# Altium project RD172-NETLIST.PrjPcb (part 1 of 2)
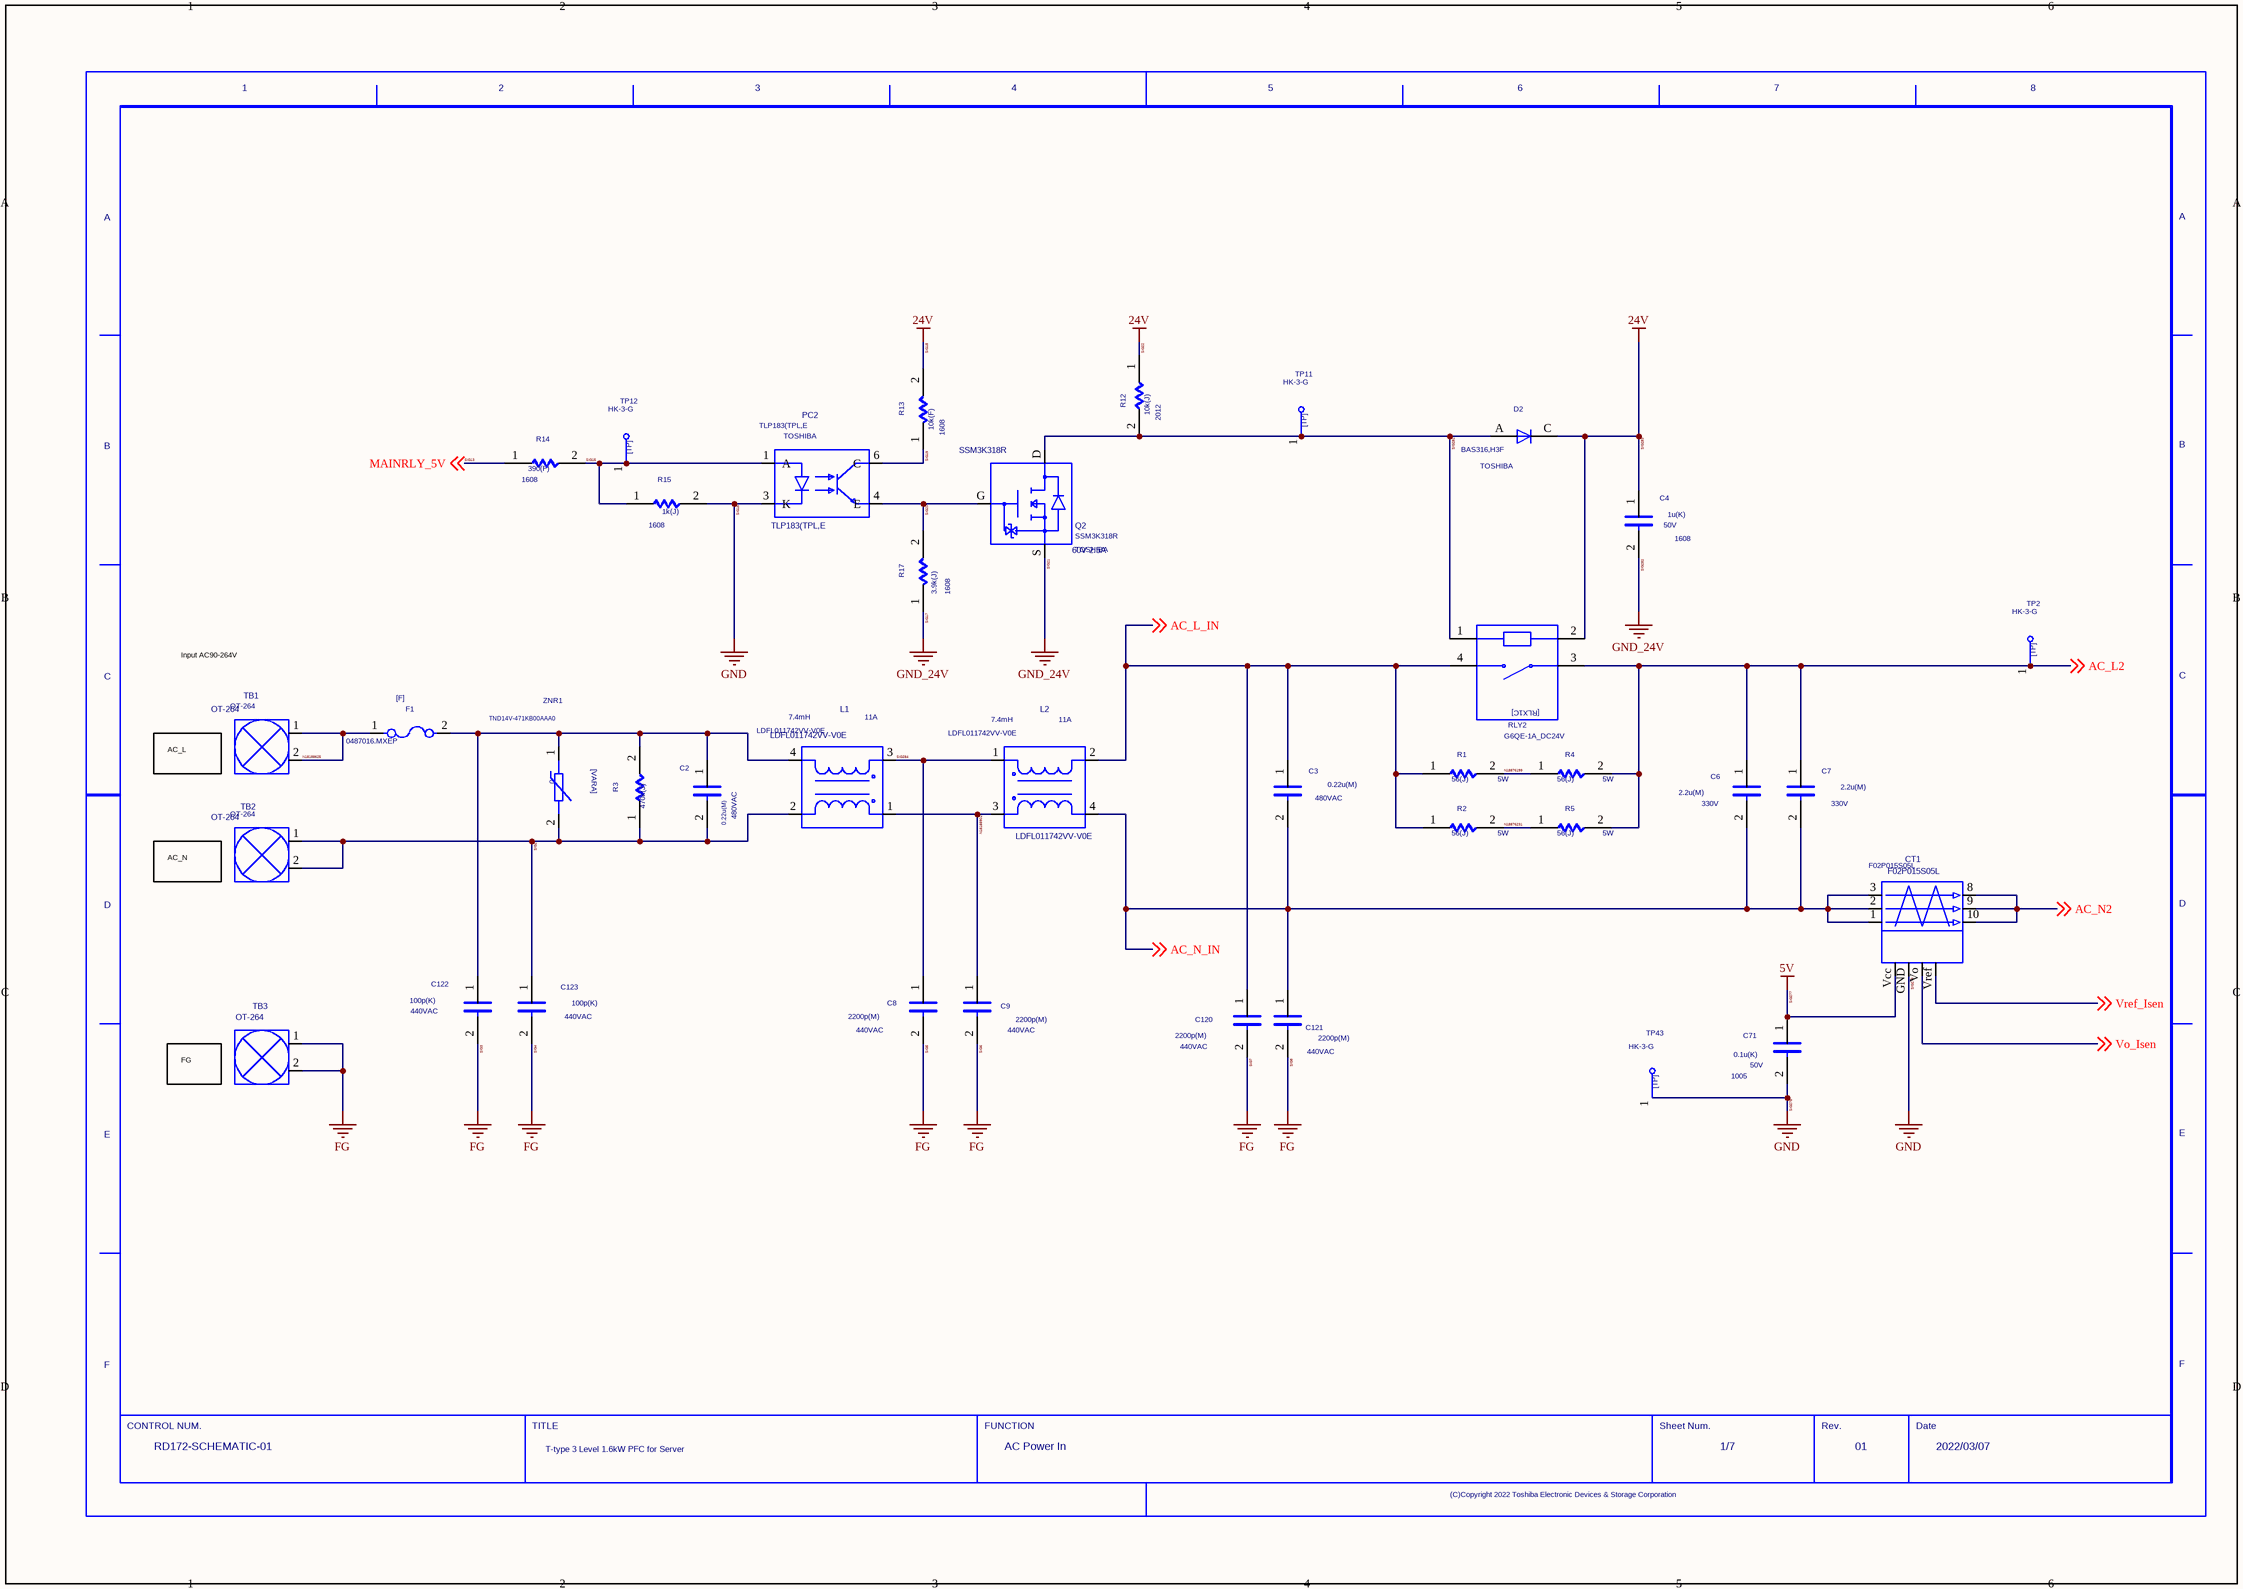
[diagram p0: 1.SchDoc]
7 sheets, 376 parts. Net scope: global (net labels, ports and power ports of the same name join across sheets).
Sheets:
  1.SchDoc
  2.SchDoc
  3.SchDoc
  4.SchDoc
  5.SchDoc
  6.SchDoc
  7.SchDoc

## Sheet 1.SchDoc
size 420 x 297 mm

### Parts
(Parts that share a designator on the sheet are numbered #1, #2 ... from top to bottom, then left to right.)
C2  VAL2: 480VAC  VAL1: 0.22u(M)  (hidden comment: C)
C3  VAL2: 480VAC  VAL1: 0.22u(M)  (hidden comment: C)
C4  SIZECODESMD: 1608  VAL2: 50V  VAL1: 1u(K)  (hidden comment: C)
C6  VAL2: 330V  VAL1: 2.2u(M)  (hidden comment: C)
C7  VAL2: 330V  VAL1: 2.2u(M)  (hidden comment: C)
C8  VAL2: 440VAC  VAL1: 2200p(M)  (hidden comment: C)
C9  VAL2: 440VAC  VAL1: 2200p(M)  (hidden comment: C)
C71  SIZECODESMD: 1005  VAL2: 50V  VAL1: 0.1u(K)  (hidden comment: C)
C120  VAL2: 440VAC  VAL1: 2200p(M)  (hidden comment: C)
C121  VAL2: 440VAC  VAL1: 2200p(M)  (hidden comment: C)
C122  VAL2: 440VAC  VAL1: 100p(K)  (hidden comment: C)
C123  VAL2: 440VAC  VAL1: 100p(K)  (hidden comment: C)
CT1  F02P015S05L
D2  VAL3: BAS316,H3F  USERCOMPTEXT3: TOSHIBA  (hidden comment: D)
F1  VAL3: 0487016.MXEP  (hidden comment: F)
L1  LDFL011742VV-V0E  VAL1: 7.4mH
L2  LDFL011742VV-V0E  VAL1: 7.4mH
PC2  TLP183(TPL,E  USERCOMPTEXT3: TOSHIBA
Q2  SSM3K318R  NOTE: 60V 2.5A  USERCOMPTEXT3: TOSHIBA
R1  VAL2: 5W  VAL1: 56(J)  (hidden comment: R)
R2  VAL2: 5W  VAL1: 56(J)  (hidden comment: R)
R3  VAL1: 470k(J)  (hidden comment: R)
R4  VAL2: 5W  VAL1: 56(J)  (hidden comment: R)
R5  VAL2: 5W  VAL1: 56(J)  (hidden comment: R)
R12  SIZECODESMD: 2012  VAL1: 10k(J)  (hidden comment: R)
R13  SIZECODESMD: 1608  VAL1: 10k(F)  (hidden comment: R)
R14  SIZECODESMD: 1608  VAL1: 390(F)  (hidden comment: R)
R15  SIZECODESMD: 1608  VAL1: 1k(J)  (hidden comment: R)
R17  SIZECODESMD: 1608  VAL1: 3.9k(J)  (hidden comment: R)
RLY2  VAL3: G6QE-1A_DC24V  (hidden comment: RLX1C)
TB1  OT-264
TB2  OT-264
TB3  OT-264
TP2  VAL3: HK-3-G  (hidden comment: TP)
TP11  VAL3: HK-3-G  (hidden comment: TP)
TP12  VAL3: HK-3-G  (hidden comment: TP)
TP43  VAL3: HK-3-G  (hidden comment: TP)
U?#1  DATE: 2022/03/07  DRAWINGNUMBER: RD172-SCHEMATIC-01  REVISION: 01  SHEETNUMBER: 1/7  TITLE: T-type 3 Level 1.6kW PFC for Server  FUNCTION: AC Power In  (hidden comment: WAKU_DEF100)
ZNR1  VAL3: TND14V-471KB00AAA0  (hidden comment: VARA)

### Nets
5V: C71.1 CT1.Vcc(VCC)  [also labelled SIG277]  [project net SIG177]
GND: C71.2 CT1.GND PC2.3(K) R15.2 TP43.1  [also labelled SIG16, SIG275, SIG278]  [project net SIG157]
SIG3: C8.2 C9.2 C120.2 C121.2 C122.2 C123.2 TB3.1 TB3.2  [also labelled FG, SIG4, SIG5, SIG6, SIG7, SIG8]
SIG17: C4.2 Q2.S R17.1  [also labelled GND_24V, SIG21, SIG282]
SIG18: C4.1 D2.C R12.1 R13.2 RLY2.2  [also labelled 24V, SIG22, SIG283]
AC_L2: C6.1 C7.1 R4.2 R5.2 RLY2.3 TP2.1 ; off-sheet AC_L2
AC_L_IN: C3.1 C120.1 L2.2 R1.1 R2.1 RLY2.4 ; off-sheet AC_L_IN
AC_N2: CT1.8 CT1.9 CT1.10 ; off-sheet AC_N2
AC_N_IN: C3.2 C6.2 C7.2 C121.1 CT1.1 CT1.2 CT1.3 L2.4 ; off-sheet AC_N_IN
N18188625: F1.1 TB1.1 TB1.2
N18188901: C9.1 L1.1 L2.3
N18876199: R1.2 R4.1
N18876231: R2.2 R5.1
SIG1: C2.1 C122.1 F1.2 L1.4 R3.2 ZNR1.1
SIG2: C2.2 C123.1 L1.2 R3.1 TB2.1 TB2.2 ZNR1.2
SIG13: R14.1 ; off-sheet MAINRLY_5V  [also labelled MAINRLY_5V]
SIG15: PC2.1(A) R14.2 R15.1 TP12.1
SIG19: PC2.6(C) R13.1
SIG20: PC2.4(E) Q2.G R17.2
SIG281: D2.A Q2.D R12.2 RLY2.1 TP11.1
SIG284: C8.1 L1.3 L2.1
Vo_Isen: CT1.Vo ; off-sheet Vo_Isen
Vref_Isen: CT1.Vref ; off-sheet Vref_Isen

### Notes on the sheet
- Input AC90-264V
- AC_L
- AC_N
- FG

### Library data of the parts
C2 C3 = C: OriginalSymbolOrigin: (2540,7620); COMP: -C-F339X142248MIP2T0
C4 = C: OriginalSymbolOrigin: (2540,7620); COMP: -C-UMK107AB7105KA-T
C6 C7 = C: OriginalSymbolOrigin: (2540,7620); COMP: -C-B32914A3225M000
C8 C9 C120 C121 = C: OriginalSymbolOrigin: (2540,7620); COMP: -C-CD45-E2GA222M-VKA
C71 = C: OriginalSymbolOrigin: (2540,7620); COMP: -C-UMK105BJ104KV-F
C122 C123 = C: OriginalSymbolOrigin: (2540,7620); COMP: -C-CD45-B2GA101K-VKA
CT1 = F02P015S05L: Current Transducer, 15A; MANUFACTURER: Tamura; COMP: -CT-F02P015S05L_PIN; TIME: 16:53:55; UPDATEUSER: t5459927; UPDATETIME: 16:08:01; SAVECOUNT: 2; SAVEAREA0: -5739,-18135,20354,994; OriginalSymbolOrigin: (0,0)
D2 = D: SAVEAREA0: -225,-91,12804,7836; SAVECOUNT: 3; TIME: 14:49:55; UPDATEUSER: 19870035; UPDATETIME: 14:20:16; OriginalSymbolOrigin: (5080,5080); COMP: -D-BAS316_H3F_AC
F1 = F: OriginalSymbolOrigin: (2540,5080); COMP: -F-0487016MXEP
L1 L2 = LDFL011742VV_V0E: 11A; MANUFACTURER: Nippon Chemi-Con; COMP: -L-LDFL011742VV-V0E; TIME: 16:53:58; UPDATEUSER: t5459927; SAVECOUNT: 1; SAVEAREA0: -3836,-15544,18528,852; OriginalSymbolOrigin: (0,0); INSTANCENAME: INS18188789
PC2 = TLP183_TPL_E: Photocoupler; COMP: -PC-TLP183_TPL_E; TIME: 16:53:54; UPDATEUSER: t5459927; UPDATETIME: 16:20:20; SAVECOUNT: 2; SAVEAREA0: -3467,-14897,20665,2795; OriginalSymbolOrigin: (0,0)
Q2 = SSM3K318R: MOSFET; COMP: -Q-SSM3K318R_LF; TIME: 16:53:56; UPDATEUSER: t5459927; UPDATETIME: 14:46:06; SAVECOUNT: 2; SAVEAREA0: -8920,-18190,20901,3672; OriginalSymbolOrigin: (0,0)
R1 R2 R4 R5 = R: OriginalSymbolOrigin: (5080,5080); COMP: -R-SQMW556RJ
R3 = R: OriginalSymbolOrigin: (5080,5080); VAL2: 1W; COMP: -R-RCR60C474J
R12 = R: OriginalSymbolOrigin: (5080,5080); COMP: -R-RK73B2ATTD103J; VAL2: 250mW
R13 = R: OriginalSymbolOrigin: (5080,5080); COMP: -R-ERJ3EKF1002V; VAL2: 100mW
R14 = R: OriginalSymbolOrigin: (5080,5080); COMP: -R-ERJ3EKF3900V; VAL2: 100mW
R15 = R: OriginalSymbolOrigin: (5080,5080); COMP: -R-RK73B1JTTD102J; VAL2: 125mW
R17 = R: OriginalSymbolOrigin: (5080,5080); COMP: -R-RK73B1JTTD392J; VAL2: 100mW
RLY2 = RLX1C: SAVECOUNT: 9; SAVEAREA0: -9347,-440,34039,23986; OriginalSymbolOrigin: (5080,20320); COMP: -RL-G6QE-1A_DC24
TB1 = OT_264: Terminal, 50A, M4; MANUFACTURER: Osada; COMP: -TB-OT-264; TIME: 16:53:54; UPDATEUSER: t5459927; SAVECOUNT: 1; SAVEAREA0: -3825,-10384,11084,546; OriginalSymbolOrigin: (0,0); REFERENCE TEMPLATE: TB; INSTANCENAME: INS18188586
TB2 = OT_264: Terminal, 50A, M4; MANUFACTURER: Osada; COMP: -TB-OT-264; TIME: 16:53:54; UPDATEUSER: t5459927; SAVECOUNT: 1; SAVEAREA0: -3825,-10384,11084,546; OriginalSymbolOrigin: (0,0); REFERENCE TEMPLATE: TB; INSTANCENAME: INS18188886
TB3 = OT_264: Terminal, 50A, M4; MANUFACTURER: Osada; COMP: -TB-OT-264; TIME: 16:53:54; UPDATEUSER: t5459927; UPDATETIME: 16:17:50; SAVECOUNT: 2; SAVEAREA0: -3825,-10384,11084,546; OriginalSymbolOrigin: (0,0)
TP2 TP11 TP12 TP43 = TP: TIME: 16:12:21; UPDATEUSER: fukuda-y; UPDATETIME: 16:18:11; SAVECOUNT: 2; SAVEAREA0: -242,-92,12810,7836; OriginalSymbolOrigin: (0,7620); COMP: -TP-HK-3-G
U?#1 = WAKU_DEF100: PLOTTIME: HH:MM; SAVEAREA0: 148187,-66180,486823,89919; TIME: 14:30:25; UPDATEUSER: t5459927; UPDATETIME: 09:34:25; SAVECOUNT: 6; OriginalSymbolOrigin: (10160,284480)
ZNR1 = VARA: SAVEAREA0: -9950,-8554,25168,13619; SAVECOUNT: 12; TIME: 09:56:50; UPDATEUSER: tomizawa-y; OriginalSymbolOrigin: (2540,5080); COMP: -ZNR-TND14V-471KB00AAA0

## Sheet 2.SchDoc
size 420 x 297 mm
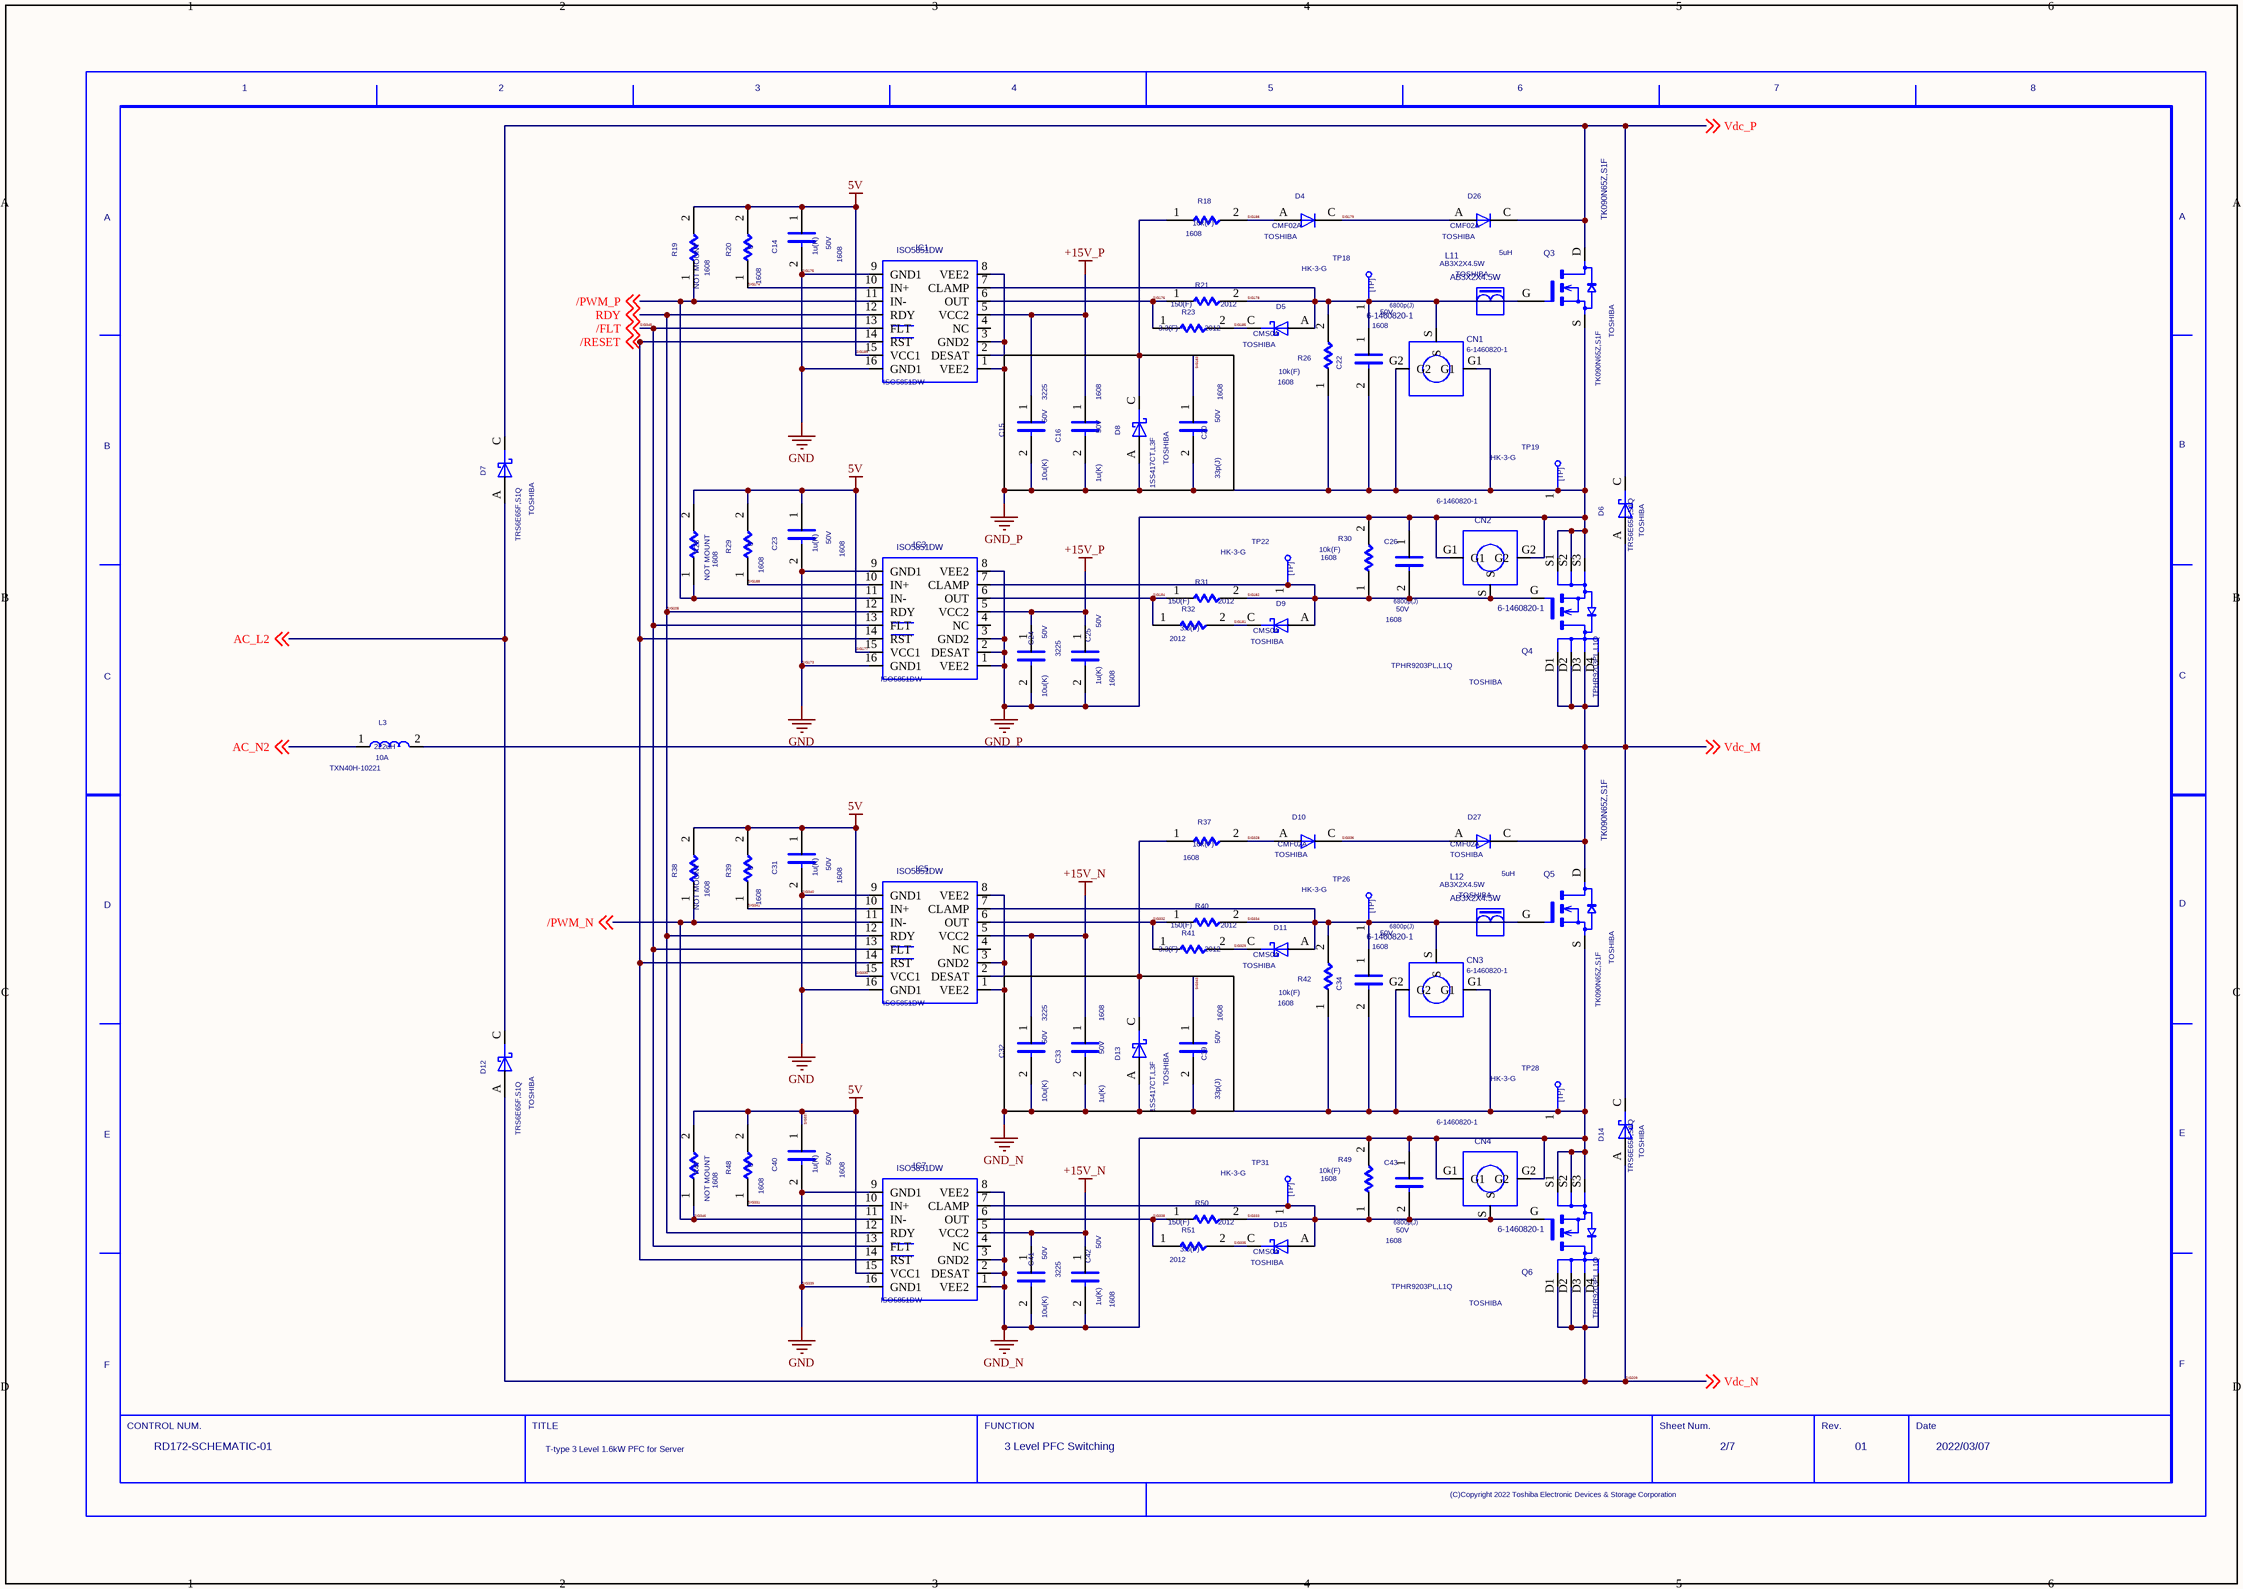
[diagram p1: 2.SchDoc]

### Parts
(Parts that share a designator on the sheet are numbered #1, #2 ... from top to bottom, then left to right.)
C14  SIZECODESMD: 1608  VAL2: 50V  VAL1: 1u(K)  (hidden comment: C)
C15  SIZECODESMD: 3225  VAL2: 50V  VAL1: 10u(K)  (hidden comment: C)
C16  SIZECODESMD: 1608  VAL2: 50V  VAL1: 1u(K)  (hidden comment: C)
C20  SIZECODESMD: 1608  VAL2: 50V  VAL1: 33p(J)  (hidden comment: C)
C22  SIZECODESMD: 1608  VAL2: 50V  VAL1: 6800p(J)  (hidden comment: C)
C23  SIZECODESMD: 1608  VAL2: 50V  VAL1: 1u(K)  (hidden comment: C)
C24  SIZECODESMD: 3225  VAL2: 50V  VAL1: 10u(K)  (hidden comment: C)
C25  SIZECODESMD: 1608  VAL2: 50V  VAL1: 1u(K)  (hidden comment: C)
C26  SIZECODESMD: 1608  VAL2: 50V  VAL1: 6800p(J)  (hidden comment: C)
C31  SIZECODESMD: 1608  VAL2: 50V  VAL1: 1u(K)  (hidden comment: C)
C32  SIZECODESMD: 3225  VAL2: 50V  VAL1: 10u(K)  (hidden comment: C)
C33  SIZECODESMD: 1608  VAL2: 50V  VAL1: 1u(K)  (hidden comment: C)
C34  SIZECODESMD: 1608  VAL2: 50V  VAL1: 6800p(J)  (hidden comment: C)
C39  SIZECODESMD: 1608  VAL2: 50V  VAL1: 33p(J)  (hidden comment: C)
C40  SIZECODESMD: 1608  VAL2: 50V  VAL1: 1u(K)  (hidden comment: C)
C41  SIZECODESMD: 3225  VAL2: 50V  VAL1: 10u(K)  (hidden comment: C)
C42  SIZECODESMD: 1608  VAL2: 50V  VAL1: 1u(K)  (hidden comment: C)
C43  SIZECODESMD: 1608  VAL2: 50V  VAL1: 6800p(J)  (hidden comment: C)
CN1  6-1460820-1
CN2  6-1460820-1
CN3  6-1460820-1
CN4  6-1460820-1
D4  VAL3: CMF02A  USERCOMPTEXT3: TOSHIBA  (hidden comment: D)
D5  USERCOMPTEXT3: TOSHIBA  VAL3: CMS04  (hidden comment: SBD)
D6  VAL3: TRS6E65F,S1Q  USERCOMPTEXT3: TOSHIBA  (hidden comment: SBD)
D7  USERCOMPTEXT3: TOSHIBA  VAL3: TRS6E65F,S1Q  (hidden comment: SBD)
D8  USERCOMPTEXT3: TOSHIBA  VAL3: 1SS417CT,L3F  (hidden comment: SBD)
D9  USERCOMPTEXT3: TOSHIBA  VAL3: CMS04  (hidden comment: SBD)
D10  VAL3: CMF02A  USERCOMPTEXT3: TOSHIBA  (hidden comment: D)
D11  USERCOMPTEXT3: TOSHIBA  VAL3: CMS04  (hidden comment: SBD)
D12  USERCOMPTEXT3: TOSHIBA  VAL3: TRS6E65F,S1Q  (hidden comment: SBD)
D13  USERCOMPTEXT3: TOSHIBA  VAL3: 1SS417CT,L3F  (hidden comment: SBD)
D14  VAL3: TRS6E65F,S1Q  USERCOMPTEXT3: TOSHIBA  (hidden comment: SBD)
D15  USERCOMPTEXT3: TOSHIBA  VAL3: CMS04  (hidden comment: SBD)
D26  VAL3: CMF02A  USERCOMPTEXT3: TOSHIBA  (hidden comment: D)
D27  VAL3: CMF02A  USERCOMPTEXT3: TOSHIBA  (hidden comment: D)
IC1  ISO5851DW
IC3  ISO5851DW
IC5  ISO5851DW
IC7  ISO5851DW
L3  VAL3: TXN40H-10221  VAL2: 10A  VAL1: 222uH  (hidden comment: L)
L11  AB3X2X4.5W  USERCOMPTEXT3: TOSHIBA  VAL1: 5uH
L12  AB3X2X4.5W  USERCOMPTEXT3: TOSHIBA  VAL1: 5uH
Q3  TK090N65Z,S1F  USERCOMPTEXT3: TOSHIBA
Q4  TPHR9203PL,L1Q  USERCOMPTEXT3: TOSHIBA
Q5  TK090N65Z,S1F  USERCOMPTEXT3: TOSHIBA
Q6  TPHR9203PL,L1Q  USERCOMPTEXT3: TOSHIBA
R18  SIZECODESMD: 1608  VAL1: 10k(F)  (hidden comment: R)
R19  SIZECODESMD: 1608  NOTMOUNT: NOT MOUNT  (hidden comment: R)
R20  SIZECODESMD: 1608  VAL1: 0  (hidden comment: R)
R21  SIZECODESMD: 2012  VAL1: 150(F)  (hidden comment: R)
R23  SIZECODESMD: 2012  VAL1: 3.3(F)  (hidden comment: R)
R26  SIZECODESMD: 1608  VAL1: 10k(F)  (hidden comment: R)
R28  SIZECODESMD: 1608  NOTMOUNT: NOT MOUNT  (hidden comment: R)
R29  SIZECODESMD: 1608  VAL1: 0  (hidden comment: R)
R30  SIZECODESMD: 1608  VAL1: 10k(F)  (hidden comment: R)
R31  SIZECODESMD: 2012  VAL1: 150(F)  (hidden comment: R)
R32  SIZECODESMD: 2012  VAL1: 3.3(F)  (hidden comment: R)
R37  SIZECODESMD: 1608  VAL1: 10k(F)  (hidden comment: R)
R38  SIZECODESMD: 1608  NOTMOUNT: NOT MOUNT  (hidden comment: R)
R39  SIZECODESMD: 1608  VAL1: 0  (hidden comment: R)
R40  SIZECODESMD: 2012  VAL1: 150(F)  (hidden comment: R)
R41  SIZECODESMD: 2012  VAL1: 3.3(F)  (hidden comment: R)
R42  SIZECODESMD: 1608  VAL1: 10k(F)  (hidden comment: R)
R47  SIZECODESMD: 1608  NOTMOUNT: NOT MOUNT  (hidden comment: R)
R48  SIZECODESMD: 1608  VAL1: 0  (hidden comment: R)
R49  SIZECODESMD: 1608  VAL1: 10k(F)  (hidden comment: R)
R50  SIZECODESMD: 2012  VAL1: 150(F)  (hidden comment: R)
R51  SIZECODESMD: 2012  VAL1: 3.3(F)  (hidden comment: R)
TP18  VAL3: HK-3-G  (hidden comment: TP)
TP19  VAL3: HK-3-G  (hidden comment: TP)
TP22  VAL3: HK-3-G  (hidden comment: TP)
TP26  VAL3: HK-3-G  (hidden comment: TP)
TP28  VAL3: HK-3-G  (hidden comment: TP)
TP31  VAL3: HK-3-G  (hidden comment: TP)
U?#2  DATE: 2022/03/07  REVISION: 01  SHEETNUMBER: 2/7  FUNCTION: 3 Level PFC Switching  TITLE: T-type 3 Level 1.6kW PFC for Server  DRAWINGNUMBER: RD172-SCHEMATIC-01  (hidden comment: WAKU_DEF100)

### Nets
+15V_N: C32.1 C33.1 C41.1 C42.1 IC5.5(VCC2) IC7.5(VCC2)
+15V_P: C15.1 C16.1 C24.1 C25.1 IC1.5(VCC2) IC3.5(VCC2)  [project net SIG306]
GND: C14.2 C23.2 C31.2 C40.2 IC1.9(GND1) IC1.16(GND1) IC3.9(GND1) IC3.16(GND1) IC5.9(GND1) IC5.16(GND1) IC7.9(GND1) IC7.16(GND1)  [also labelled SIG173, SIG175, SIG339, SIG340]  [project net SIG157]
GND_N: C32.2 C33.2 C34.2 C39.2 C41.2 C42.2 C43.1 CN3.G1 CN3.G2 CN4.G1 CN4.G2 D13.A IC5.1(VEE2) IC5.3(GND2) IC5.8(VEE2) IC7.1(VEE2) IC7.2(DESAT) IC7.3(GND2) IC7.8(VEE2) Q5.S Q6.S1 Q6.S2 Q6.S3 R42.1 R49.2 TP28.1
GND_P: C15.2 C16.2 C20.2 C22.2 C24.2 C25.2 C26.1 CN1.G1 CN1.G2 CN2.G1 CN2.G2 D8.A IC1.1(VEE2) IC1.3(GND2) IC1.8(VEE2) IC3.1(VEE2) IC3.2(DESAT) IC3.3(GND2) IC3.8(VEE2) Q3.S Q4.S1 Q4.S2 Q4.S3 R26.1 R30.2 TP19.1  [project net SIG307]
SIG177: C14.1 C23.1 C31.1 C40.1 IC1.15(VCC1) IC3.15(VCC1) IC5.15(VCC1) IC7.15(VCC1) R19.2 R20.2 R28.2 R29.2 R38.2 R39.2 R47.2 R48.2  [also labelled 5V, SIG189, SIG330, SIG337]
/PWM_P: IC1.11(IN-) IC3.11(IN-) R19.1 R28.1 ; off-sheet /PWM_P
/RESET: IC1.14(RST) IC3.14(RST) IC5.14(RST) IC7.14(RST) ; off-sheet /RESET
AC_L2: D7.A D12.C ; off-sheet AC_L2
AC_N2: L3.1 ; off-sheet AC_N2
SIG174: IC1.10(IN+) R20.1
SIG176: IC1.6(OUT) R21.1 R23.1
SIG178: C22.1 CN1.S D5.A IC1.7(CLAMP) Q3.G R21.2 R26.2 TP18.1
SIG179: D4.C D26.A
SIG181: D9.C R32.2
SIG182: C26.2 CN2.S D9.A IC3.7(CLAMP) Q4.G R30.1 R31.2 TP22.1
SIG183: C20.1 D8.C IC1.2(DESAT) R18.1
SIG184: IC3.6(OUT) R31.1 R32.1
SIG185: D5.C R23.2
SIG186: D4.A R18.2
SIG188: IC3.10(IN+) R29.1
SIG205: IC1.12(RDY) IC3.12(RDY) IC5.12(RDY) IC7.12(RDY) ; off-sheet RDY  [also labelled RDY]
SIG209: D12.A D14.A Q6.D1 Q6.D2 Q6.D3 Q6.D4 ; off-sheet Vdc_N  [also labelled Vdc_N]
SIG328: D10.A R37.2
SIG329: D11.C R41.2
SIG331: IC7.10(IN+) R48.1
SIG332: IC5.6(OUT) R40.1 R41.1
SIG333: C43.2 CN4.S D15.A IC7.7(CLAMP) Q6.G R49.1 R50.2 TP31.1
SIG334: C34.1 CN3.S D11.A IC5.7(CLAMP) Q5.G R40.2 R42.2 TP26.1
SIG335: D15.C R51.2
SIG336: D10.C D27.A
SIG338: IC7.6(OUT) R50.1 R51.1
SIG341: IC5.10(IN+) R39.1
SIG343: C39.1 D13.C IC5.2(DESAT) R37.1
SIG345: IC1.13(FLT) IC3.13(FLT) IC5.13(FLT) IC7.13(FLT) ; off-sheet /FLT  [also labelled /FLT]
SIG346: IC5.11(IN-) IC7.11(IN-) R38.1 R47.1 ; off-sheet /PWM_N  [also labelled /PWM_N]
Vdc_M: D6.A D14.C D27.C L3.2 Q4.D1 Q4.D2 Q4.D3 Q4.D4 Q5.D ; off-sheet Vdc_M
Vdc_P: D6.C D7.C D26.C Q3.D ; off-sheet Vdc_P

Not connected (* = marked no-connect by the designer): IC1 4(NC); IC3 4(NC); IC5 4(NC); IC7 4(NC)

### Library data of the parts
C14 C16 C23 C25 C31 C33 C40 C42 = C: as C4 on sheet 1
C15 C24 C32 C41 = C: OriginalSymbolOrigin: (2540,7620); COMP: -C-UMK325AB7106KM-T
C20 C39 = C: OriginalSymbolOrigin: (2540,7620); COMP: -C-CGA3E2C0G1H330J080AA
C22 C26 C34 C43 = C: OriginalSymbolOrigin: (2540,7620); COMP: -C-GRM1885C1H682JA01D
CN1-CN4 = 6_1460820_1: MMCX Connector, 170V; MANUFACTURER: TE Connectivity; COMP: -CN-6-1460820-1; TIME: 16:53:54; UPDATEUSER: t5459927; UPDATETIME: 16:17:04; SAVECOUNT: 3; SAVEAREA0: -4427,-12981,14210,683; OriginalSymbolOrigin: (0,0)
D4 D10 D26 D27 = D: SAVEAREA0: -225,-91,12804,7836; SAVECOUNT: 3; TIME: 14:49:55; UPDATEUSER: 19870035; UPDATETIME: 14:20:16; OriginalSymbolOrigin: (5080,5080); COMP: -D-CMF05_AC
D5 D9 D11 D15 = SBD: SAVEAREA0: -4630,-153,17114,13055; TIME: 14:49:55; UPDATEUSER: fukuda-y; UPDATETIME: 08:16:22; SAVECOUNT: 9; OriginalSymbolOrigin: (5080,5080); COMP: -D-CMS04_TE12L_Q_AC; VAL1: CMS04(TE12L,Q,M)
D6 D7 D12 D14 = SBD: SAVEAREA0: -4630,-153,17114,13055; TIME: 14:49:55; UPDATEUSER: fukuda-y; UPDATETIME: 08:16:22; SAVECOUNT: 9; OriginalSymbolOrigin: (5080,5080); COMP: -D-TRS6E65F_S1Q_AC
D8 D13 = SBD: SAVEAREA0: -4630,-153,17114,13055; TIME: 14:49:55; UPDATEUSER: fukuda-y; UPDATETIME: 08:16:22; SAVECOUNT: 9; OriginalSymbolOrigin: (5080,5080); COMP: -D-1SS417CTL3F_AC
IC1 IC3 IC5 IC7 = ISO5851DW: Gate Driver; MANUFACTURER: Txsas Instruments; COMP: -IC-ISO5851DWR; TIME: 16:53:55; UPDATEUSER: t5459927; UPDATETIME: 16:13:36; SAVECOUNT: 2; SAVEAREA0: -16530,-29444,33798,7453; OriginalSymbolOrigin: (0,0)
L3 = L: OriginalSymbolOrigin: (2540,5080); COMP: -L-TXN40H-10221
L11 L12 = AB3X2X4_5W: AMOBEADS; TIME: 16:53:53; UPDATEUSER: t5459927; SAVECOUNT: 1; SAVEAREA0: -1267,-5201,6185,262; OriginalSymbolOrigin: (0,0); INSTANCENAME: INS19006446
Q3 Q5 = TK090N65Z,S1F: Power MOS FET; COMP: -Q-TK090N65Z; NOTE: 650V 30A; TIME: 16:53:56; UPDATEUSER: t5459927; SAVECOUNT: 1; OriginalSymbolOrigin: (0,0); INSTANCENAME: INS18162118
Q4 Q6 = TPHR9203PL,L1Q: Power MOS FET; COMP: -Q-TPHR9203PL_GDS; NOTE: 30V, 150A; TIME: 16:53:55; UPDATEUSER: t5459927; SAVECOUNT: 1; OriginalSymbolOrigin: (0,0); INSTANCENAME: INS18653275
R18 R37 = R: as R13 on sheet 1
R19 R28 R38 R47 = R: OriginalSymbolOrigin: (5080,5080); COMP: -R-NC_R1608
R20 R29 R39 R48 = R: OriginalSymbolOrigin: (5080,5080); VAL2: 1A; COMP: -R-RK73Z1JTTD
R21 R31 R40 R50 = R: OriginalSymbolOrigin: (5080,5080); COMP: -R-RK73H2ATTD1500F; VAL2: 250mW
R23 R32 R41 R51 = R: OriginalSymbolOrigin: (5080,5080); COMP: -R-ERJ6DQF3R3V; VAL2: 500mW
R26 R30 R42 R49 = R: OriginalSymbolOrigin: (5080,5080); VAL2: 100mW; COMP: -R-ERJ3EKF1002V
TP18 TP19 TP22 TP26 TP28 TP31 = TP: as TP2 on sheet 1
U?#2 = WAKU_DEF100: PLOTTIME: HH:MM; SAVEAREA0: 148187,-66180,486823,89919; TIME: 14:30:25; UPDATEUSER: t5459927; UPDATETIME: 09:34:24; SAVECOUNT: 6; OriginalSymbolOrigin: (10160,284480)

## Sheet 3.SchDoc
size 420 x 297 mm
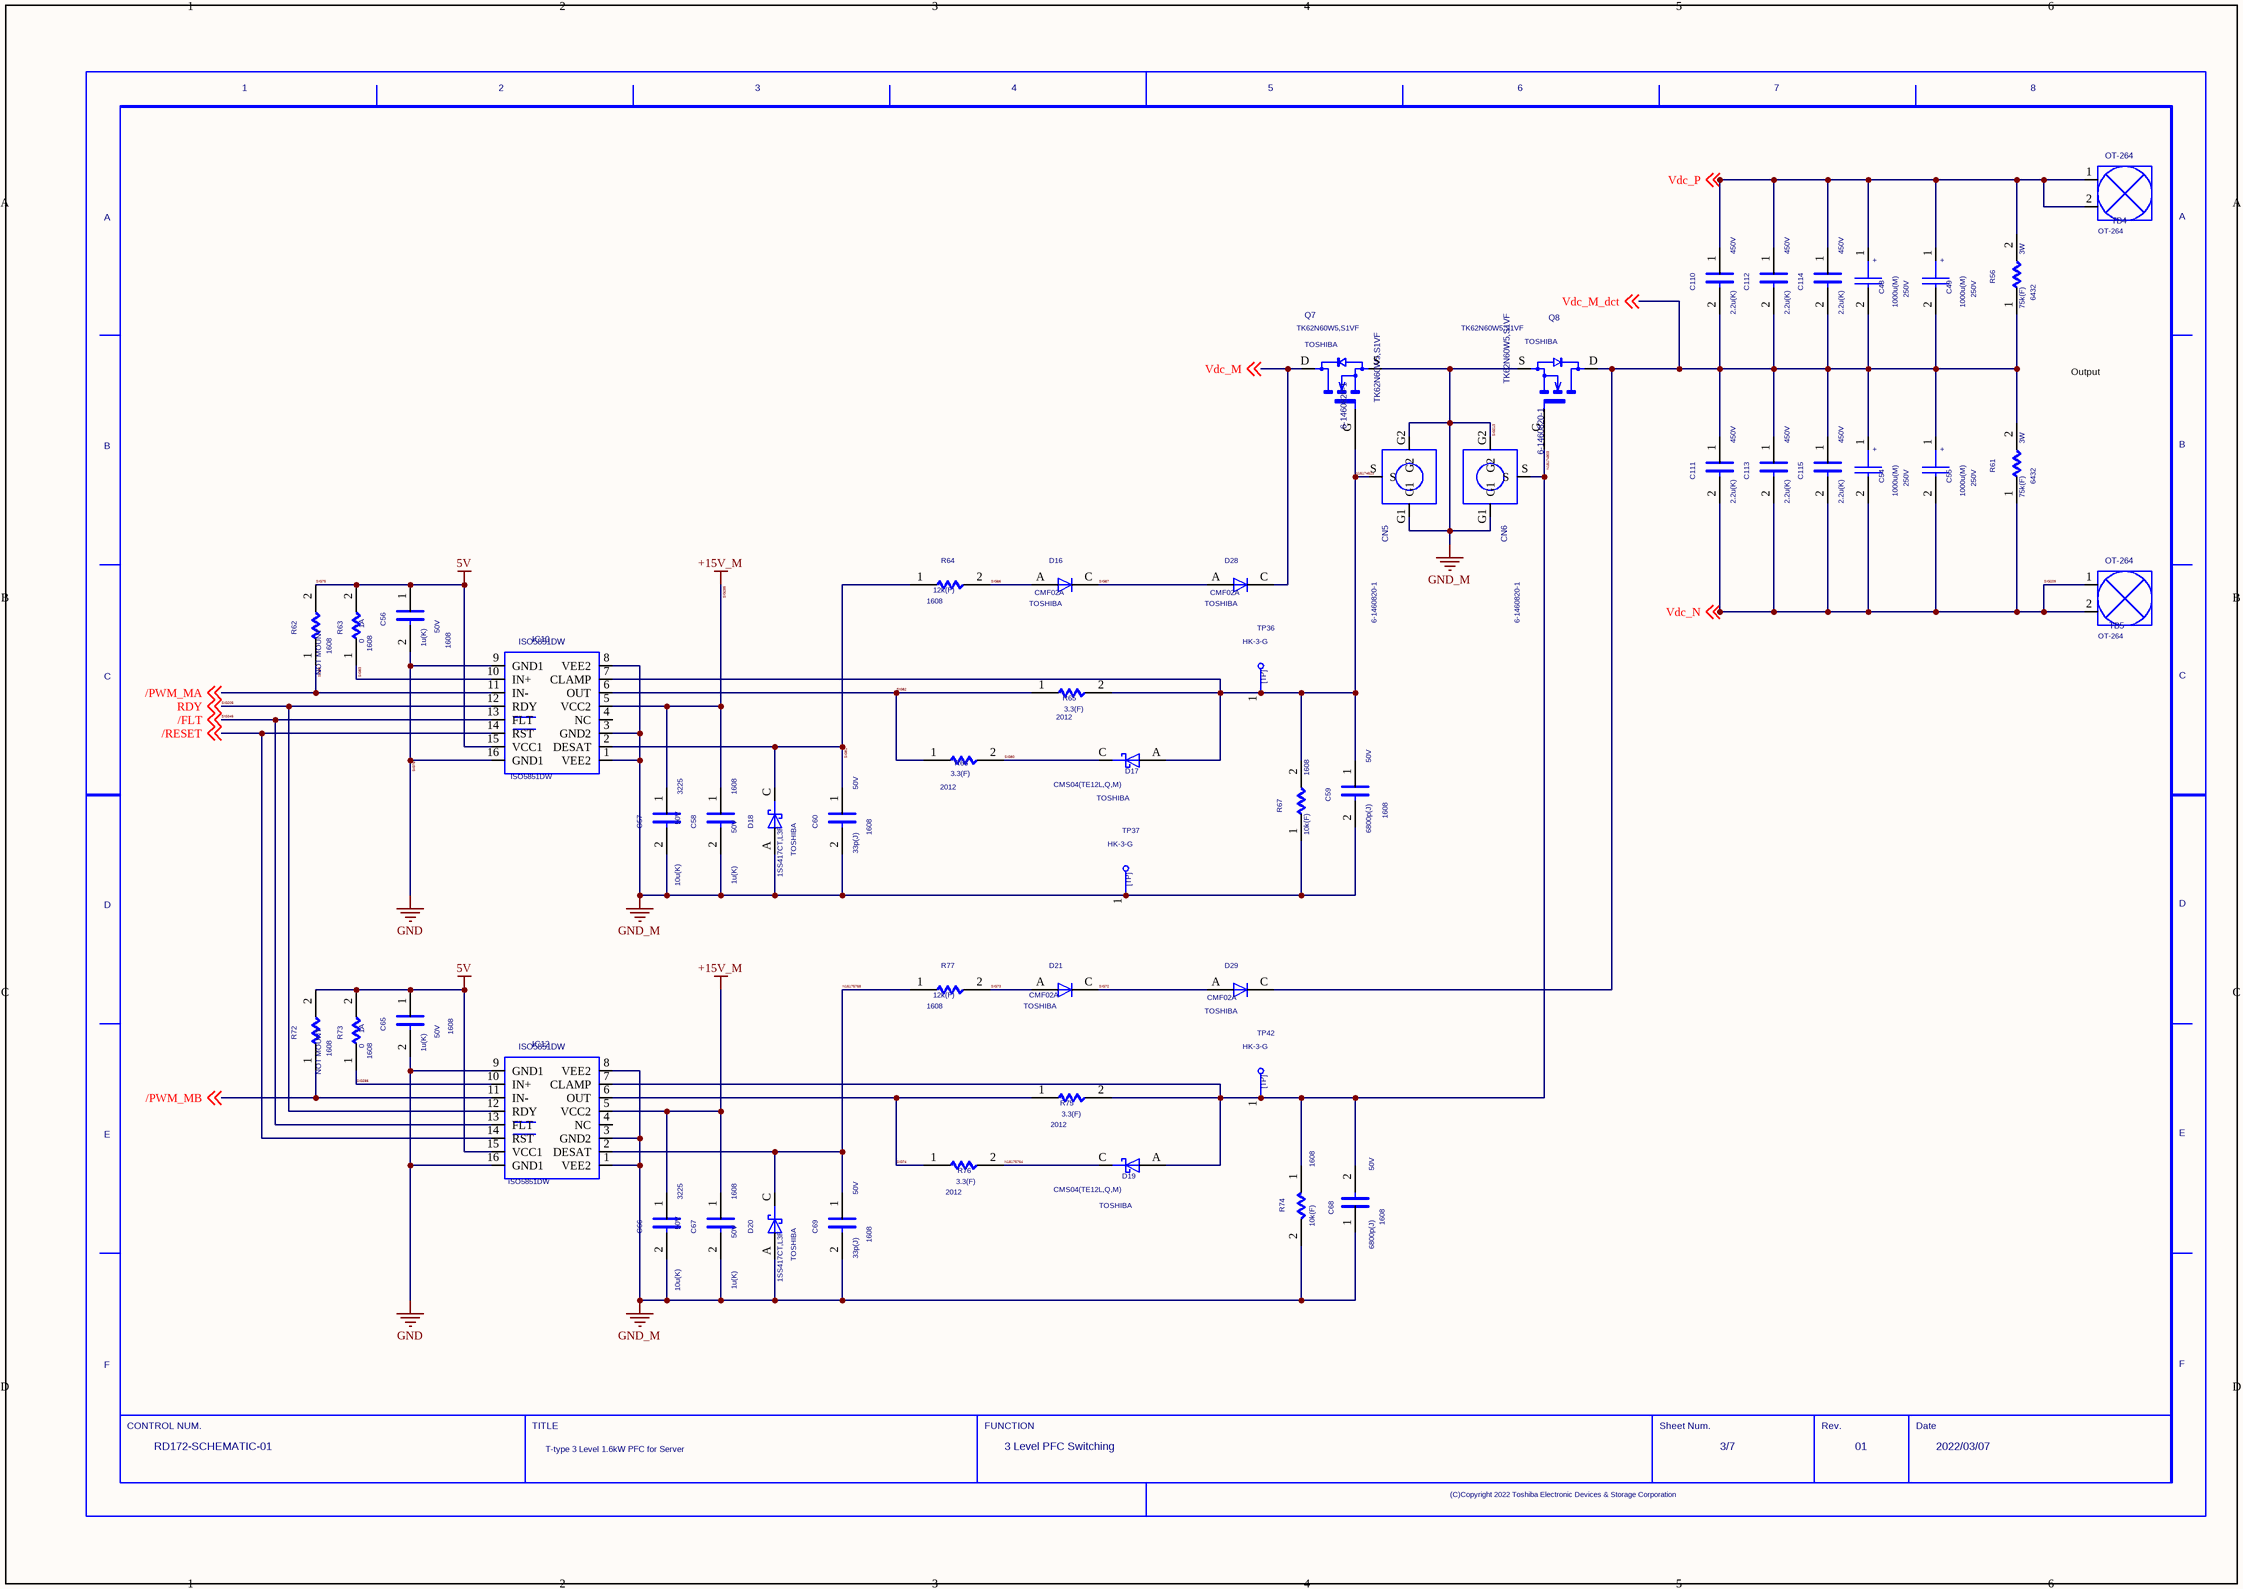
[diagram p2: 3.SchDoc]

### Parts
(Parts that share a designator on the sheet are numbered #1, #2 ... from top to bottom, then left to right.)
C48  VAL2: 250V  VAL1: 1000u(M)  (hidden comment: CP)
C49  VAL2: 250V  VAL1: 1000u(M)  (hidden comment: CP)
C54  VAL2: 250V  VAL1: 1000u(M)  (hidden comment: CP)
C55  VAL2: 250V  VAL1: 1000u(M)  (hidden comment: CP)
C56  SIZECODESMD: 1608  VAL2: 50V  VAL1: 1u(K)  (hidden comment: C)
C57  SIZECODESMD: 3225  VAL2: 50V  VAL1: 10u(K)  (hidden comment: C)
C58  SIZECODESMD: 1608  VAL2: 50V  VAL1: 1u(K)  (hidden comment: C)
C59  SIZECODESMD: 1608  VAL2: 50V  VAL1: 6800p(J)  (hidden comment: C)
C60  SIZECODESMD: 1608  VAL2: 50V  VAL1: 33p(J)  (hidden comment: C)
C65  SIZECODESMD: 1608  VAL2: 50V  VAL1: 1u(K)  (hidden comment: C)
C66  SIZECODESMD: 3225  VAL2: 50V  VAL1: 10u(K)  (hidden comment: C)
C67  SIZECODESMD: 1608  VAL2: 50V  VAL1: 1u(K)  (hidden comment: C)
C68  SIZECODESMD: 1608  VAL2: 50V  VAL1: 6800p(J)  (hidden comment: C)
C69  SIZECODESMD: 1608  VAL2: 50V  VAL1: 33p(J)  (hidden comment: C)
C110  VAL2: 450V  VAL1: 2.2u(K)  (hidden comment: C)
C111  VAL2: 450V  VAL1: 2.2u(K)  (hidden comment: C)
C112  VAL2: 450V  VAL1: 2.2u(K)  (hidden comment: C)
C113  VAL2: 450V  VAL1: 2.2u(K)  (hidden comment: C)
C114  VAL2: 450V  VAL1: 2.2u(K)  (hidden comment: C)
C115  VAL2: 450V  VAL1: 2.2u(K)  (hidden comment: C)
CN5  6-1460820-1
CN6  6-1460820-1
D16  USERCOMPTEXT3: TOSHIBA  VAL3: CMF02A  (hidden comment: D)
D17  VAL3: CMS04(TE12L,Q,M)  USERCOMPTEXT3: TOSHIBA  (hidden comment: SBD)
D18  VAL3: 1SS417CT,L3F  USERCOMPTEXT3: TOSHIBA  (hidden comment: SBD)
D19  VAL3: CMS04(TE12L,Q,M)  USERCOMPTEXT3: TOSHIBA  (hidden comment: SBD)
D20  VAL3: 1SS417CT,L3F  USERCOMPTEXT3: TOSHIBA  (hidden comment: SBD)
D21  USERCOMPTEXT3: TOSHIBA  VAL3: CMF02A  (hidden comment: D)
D28  USERCOMPTEXT3: TOSHIBA  VAL3: CMF02A  (hidden comment: D)
D29  USERCOMPTEXT3: TOSHIBA  VAL3: CMF02A  (hidden comment: D)
IC10  ISO5851DW
IC12  ISO5851DW
Q7  TK62N60W5,S1VF  USERCOMPTEXT3: TOSHIBA
Q8  TK62N60W5,S1VF  USERCOMPTEXT3: TOSHIBA
R56  SIZECODESMD: 6432  VAL2: 3W  VAL1: 75k(F)  (hidden comment: R)
R61  SIZECODESMD: 6432  VAL2: 3W  VAL1: 75k(F)  (hidden comment: R)
R62  SIZECODESMD: 1608  NOTMOUNT: NOT MOUNT  (hidden comment: R)
R63  SIZECODESMD: 1608  VAL2: 1A  VAL1: 0  (hidden comment: R)
R64  SIZECODESMD: 1608  VAL1: 12k(F)  (hidden comment: R)
R65  SIZECODESMD: 2012  VAL1: 3.3(F)  (hidden comment: R)
R66  SIZECODESMD: 2012  VAL1: 3.3(F)  (hidden comment: R)
R67  SIZECODESMD: 1608  VAL1: 10k(F)  (hidden comment: R)
R72  SIZECODESMD: 1608  NOTMOUNT: NOT MOUNT  (hidden comment: R)
R73  SIZECODESMD: 1608  VAL2: 1A  VAL1: 0  (hidden comment: R)
R74  SIZECODESMD: 1608  VAL1: 10k(F)  (hidden comment: R)
R75  SIZECODESMD: 2012  VAL1: 3.3(F)  (hidden comment: R)
R76  SIZECODESMD: 2012  VAL1: 3.3(F)  (hidden comment: R)
R77  SIZECODESMD: 1608  VAL1: 12k(F)  (hidden comment: R)
TB4  OT-264
TB5  OT-264
TP36  VAL3: HK-3-G  (hidden comment: TP)
TP37  VAL3: HK-3-G  (hidden comment: TP)
TP42  VAL3: HK-3-G  (hidden comment: TP)
U?#3  DATE: 2022/03/07  REVISION: 01  SHEETNUMBER: 3/7  FUNCTION: 3 Level PFC Switching  TITLE: T-type 3 Level 1.6kW PFC for Server  DRAWINGNUMBER: RD172-SCHEMATIC-01  (hidden comment: WAKU_DEF100)

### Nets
5V: C56.1 C65.1 IC10.15(VCC1) IC12.15(VCC1) R62.2 R63.2 R72.2 R73.2  [also labelled SIG75]  [project net SIG177]
GND: C56.2 C65.2 IC10.9(GND1) IC10.16(GND1) IC12.9(GND1) IC12.16(GND1)  [also labelled SIG78]  [project net SIG157]
SIG213: C57.2 C58.2 C59.2 C60.2 C66.2 C67.2 C68.1 C69.2 CN5.G1 CN5.G2 CN6.G1 CN6.G2 D18.A D20.A IC10.1(VEE2) IC10.3(GND2) IC10.8(VEE2) IC12.1(VEE2) IC12.3(GND2) IC12.8(VEE2) Q7.S Q8.S R67.1 R74.2 TP37.1  [also labelled GND_M]
SIG285: C57.1 C58.1 C66.1 C67.1 IC10.5(VCC2) IC12.5(VCC2)  [also labelled +15V_M]
/PWM_MB: IC12.11(IN-) R72.1 ; off-sheet /PWM_MB
/RESET: IC10.14(RST) IC12.14(RST) ; off-sheet /RESET
N18174803: C68.2 CN6.S D19.A IC12.7(CLAMP) Q8.G R74.1 R75.2 TP42.1
N18174813: C59.1 CN5.S D17.A IC10.7(CLAMP) Q7.G R65.2 R67.2 TP36.1
N18175764: D19.C R76.2
N18175788: C69.1 D20.C IC12.2(DESAT) R77.1
SIG72: D21.C D29.A
SIG73: D21.A R77.2
SIG74: IC12.6(OUT) R75.1 R76.1
SIG80: D17.C R66.2
SIG81: C60.1 D18.C IC10.2(DESAT) R64.1
SIG82: IC10.6(OUT) R65.1 R66.1
SIG83: IC10.10(IN+) R63.1
SIG84: IC10.11(IN-) R62.1 ; off-sheet /PWM_MA  [also labelled /PWM_MA]
SIG86: D16.A R64.2
SIG87: D16.C D28.A
SIG205: IC10.12(RDY) IC12.12(RDY) ; off-sheet RDY  [also labelled RDY]
SIG209: C54.2 C55.2 C111.2 C113.2 C115.2 R61.1 TB5.1 TB5.2 ; off-sheet Vdc_N  [also labelled Vdc_N]
SIG286: IC12.10(IN+) R73.1
SIG345: IC10.13(FLT) IC12.13(FLT) ; off-sheet /FLT  [also labelled /FLT]
Vdc_M: D28.C Q7.D ; off-sheet Vdc_M
Vdc_M_dct: C48.2 C49.2 C54.1 C55.1 C110.2 C111.1 C112.2 C113.1 C114.2 C115.1 D29.C Q8.D R56.1 R61.2 ; off-sheet Vdc_M_dct
Vdc_P: C48.1 C49.1 C110.1 C112.1 C114.1 R56.2 TB4.1 TB4.2 ; off-sheet Vdc_P

Not connected (* = marked no-connect by the designer): IC10 4(NC); IC12 4(NC)

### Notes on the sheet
- Output
  DC380V

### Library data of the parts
C48 C49 C54 C55 = CP: SAVEAREA0: -1450,-153,20294,13055; SAVECOUNT: 52; TIME: 15:02:55; UPDATEUSER: fukuda-y; UPDATETIME: 16:13:42; OriginalSymbolOrigin: (2540,10160); COMP: -C-LGW2E102MELC35
C56 C58 C65 C67 = C: as C4 on sheet 1
C57 C66 = C: as C15 on sheet 2
C59 C68 = C: as C22 on sheet 2
C60 C69 = C: as C20 on sheet 2
C110-C115 = C: OriginalSymbolOrigin: (2540,7620); COMP: -C-C5750X6S2W225K250KA
CN5 CN6 = 6_1460820_1: as CN1 on sheet 2
D16 D21 D28 D29 = D: as D4 on sheet 2
D17 D19 = SBD: SAVEAREA0: -4630,-153,17114,13055; TIME: 14:49:55; UPDATEUSER: fukuda-y; UPDATETIME: 08:16:22; SAVECOUNT: 9; OriginalSymbolOrigin: (5080,5080); COMP: -D-CMS04_TE12L_Q_AC
D18 D20 = SBD: as D8 on sheet 2
IC10 IC12 = ISO5851DW: as IC1 on sheet 2
Q7 = TK62N60W5,S1VF: Nch MOSFET; COMP: -Q-TK62N60W5; NOTE: 600V 61.8A; TIME: 16:53:55; UPDATEUSER: t5459927; SAVECOUNT: 1; OriginalSymbolOrigin: (0,0); INSTANCENAME: INS18652567
Q8 = TK62N60W5,S1VF: Nch MOSFET; COMP: -Q-TK62N60W5; NOTE: 600V 61.8A; TIME: 16:53:55; UPDATEUSER: t5459927; SAVECOUNT: 1; OriginalSymbolOrigin: (0,0); INSTANCENAME: INS18652910
R56 R61 = R: OriginalSymbolOrigin: (5080,5080); COMP: -R-352227KFT
R62 R72 = R: as R19 on sheet 2
R63 R73 = R: OriginalSymbolOrigin: (5080,5080); COMP: -R-RK73Z1JTTD
R64 R77 = R: OriginalSymbolOrigin: (5080,5080); COMP: -R-ERJ3EKF1202V; VAL2: 100mW
R65 R66 R75 R76 = R: as R23 on sheet 2
R67 R74 = R: as R13 on sheet 1
TB4 = OT_264: Terminal, 50A, M4; MANUFACTURER: Osada; COMP: -TB-OT-264; TIME: 16:53:54; UPDATEUSER: t5459927; SAVECOUNT: 1; SAVEAREA0: -3825,-10384,11084,546; OriginalSymbolOrigin: (0,0); REFERENCE TEMPLATE: TB; INSTANCENAME: INS18174423
TB5 = OT_264: Terminal, 50A, M4; MANUFACTURER: Osada; COMP: -TB-OT-264; TIME: 16:53:54; UPDATEUSER: t5459927; SAVECOUNT: 1; SAVEAREA0: -3825,-10384,11084,546; OriginalSymbolOrigin: (0,0); REFERENCE TEMPLATE: TB; INSTANCENAME: INS18174903
TP36 TP37 TP42 = TP: as TP2 on sheet 1
U?#3 = WAKU_DEF100: as U?#2 on sheet 2

## Sheet 4.SchDoc
size 420 x 297 mm
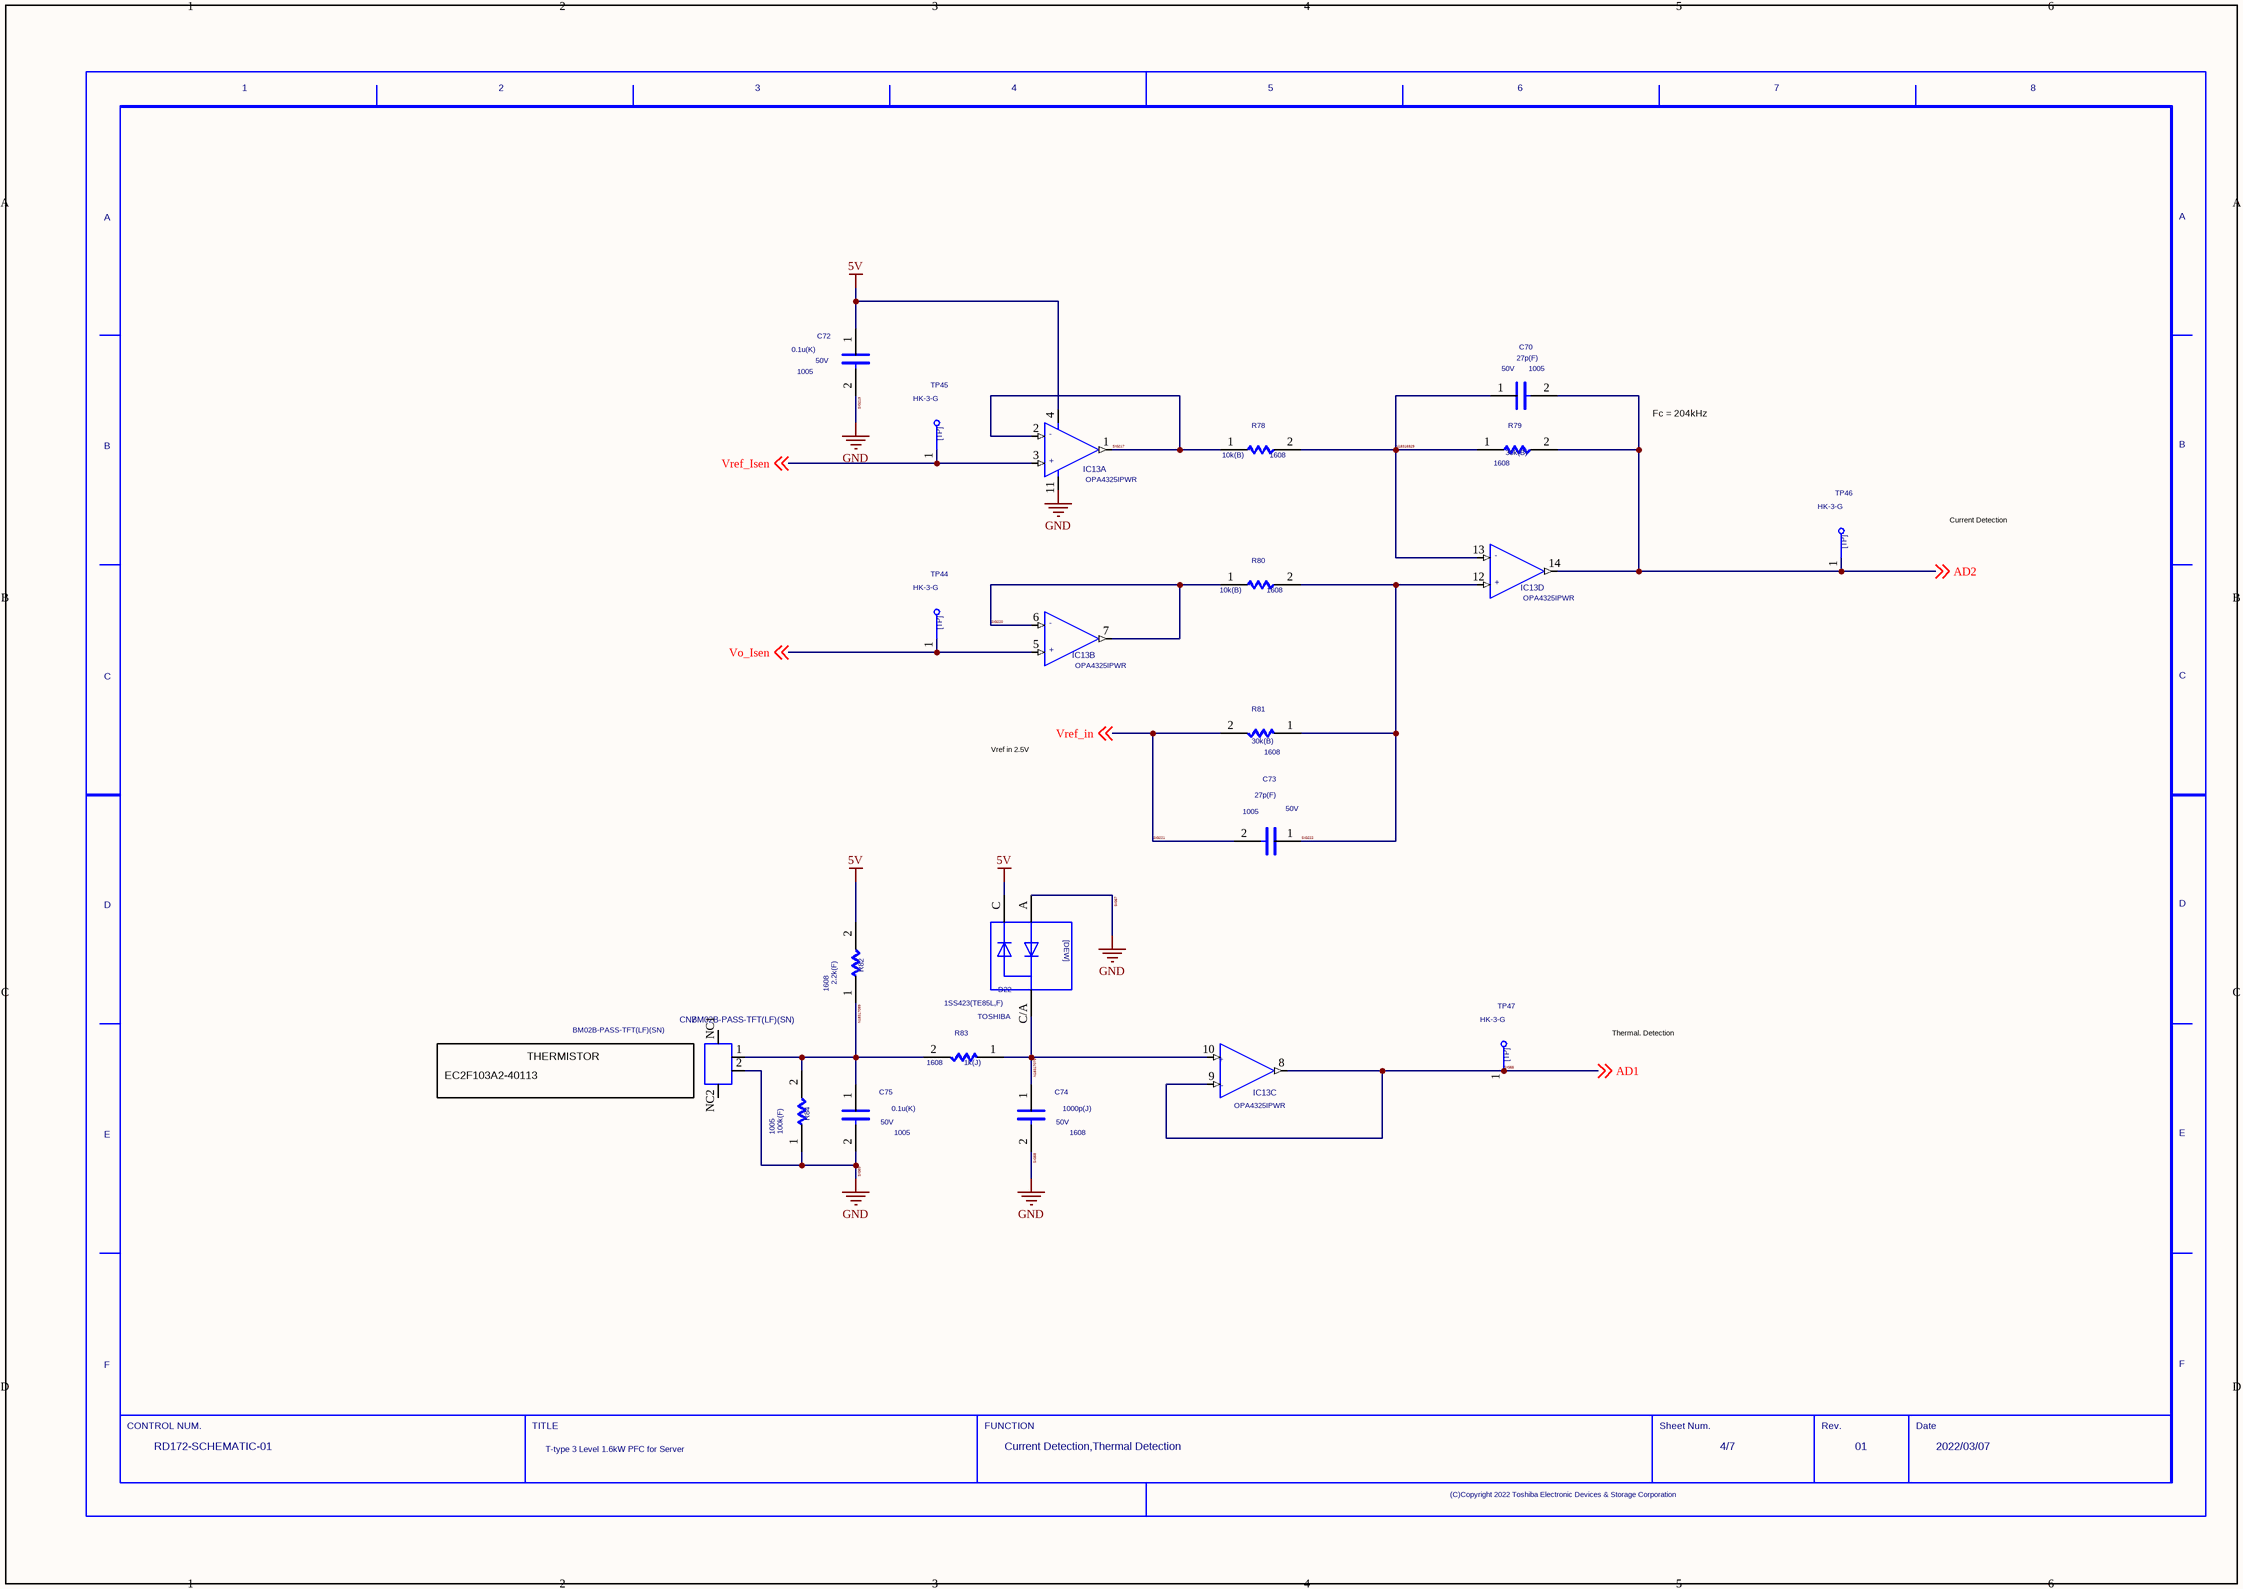
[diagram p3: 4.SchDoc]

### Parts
(Parts that share a designator on the sheet are numbered #1, #2 ... from top to bottom, then left to right.)
C70  SIZECODESMD: 1005  VAL2: 50V  VAL1: 27p(F)  (hidden comment: C)
C72  SIZECODESMD: 1005  VAL2: 50V  VAL1: 0.1u(K)  (hidden comment: C)
C73  SIZECODESMD: 1005  VAL2: 50V  VAL1: 27p(F)  (hidden comment: C)
C74  SIZECODESMD: 1608  VAL2: 50V  VAL1: 1000p(J)  (hidden comment: C)
C75  SIZECODESMD: 1005  VAL2: 50V  VAL1: 0.1u(K)  (hidden comment: C)
CN7  BM02B-PASS-TFT(LF)(SN)
D22  USERCOMPTEXT3: TOSHIBA  VAL3: 1SS423(TE85L,F)  (hidden comment: DEW)
IC13  VAL3: OPA4325IPWR  (hidden comment: OPA4325IPWR_4)  (parts A,B,C,D of 4)
R78  SIZECODESMD: 1608  VAL1: 10k(B)  (hidden comment: R)
R79  SIZECODESMD: 1608  VAL1: 30k(B)  (hidden comment: R)
R80  SIZECODESMD: 1608  VAL1: 10k(B)  (hidden comment: R)
R81  SIZECODESMD: 1608  VAL1: 30k(B)  (hidden comment: R)
R82  SIZECODESMD: 1608  VAL1: 2.2k(F)  (hidden comment: R)
R83  SIZECODESMD: 1608  VAL1: 1k(J)  (hidden comment: R)
R84  SIZECODESMD: 1005  VAL1: 100k(F)  (hidden comment: R)
TP44  VAL3: HK-3-G  (hidden comment: TP)
TP45  VAL3: HK-3-G  (hidden comment: TP)
TP46  VAL3: HK-3-G  (hidden comment: TP)
TP47  VAL3: HK-3-G  (hidden comment: TP)
U?#4  DATE: 2022/03/07  REVISION: 01  SHEETNUMBER: 4/7  FUNCTION: Current Detection,Thermal Detection  TITLE: T-type 3 Level 1.6kW PFC for Server  DRAWINGNUMBER: RD172-SCHEMATIC-01  (hidden comment: WAKU_DEF100)

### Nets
5V: C72.1 D22.C IC13.4(V+) R82.2  [project net SIG177]
GND: C72.2 C74.2 C75.2 CN7.2 D22.A IC13.11(V-) R84.1  [also labelled SIG219, SIG57, SIG58, SIG59]  [project net SIG157]
AD2: C70.2 IC13.14 R79.2 TP46.1 ; off-sheet AD2
N18316829: C70.1 IC13.13 R78.2 R79.1
N18317079: C74.1 D22.C/A(AC) IC13.10 R83.1
N18317089: C75.1 CN7.1 R82.1 R83.2 R84.2
SIG55: IC13.8 IC13.9 TP47.1 ; off-sheet AD1  [also labelled AD1]
SIG217: IC13.1(OUT) IC13.2(IN-) R78.1
SIG220: IC13.6 IC13.7 R80.1
SIG221: C73.2 R81.2 ; off-sheet Vref_in  [also labelled Vref_in]
SIG222: C73.1 IC13.12 R80.2 R81.1
Vo_Isen: IC13.5 TP44.1 ; off-sheet Vo_Isen
Vref_Isen: IC13.3(IN+) TP45.1 ; off-sheet Vref_Isen

Not connected (* = marked no-connect by the designer): CN7 NC1(PAD1) NC2(PAD2)

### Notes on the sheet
- Fc = 204kHz
- Current Detection
- Vref in 2.5V
- THERMISTOR
- Thermal. Detection
- EC2F103A2-40113

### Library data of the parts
C70 C73 = C: OriginalSymbolOrigin: (2540,7620); COMP: -C-GCM1555C1H270FA16D
C72 C75 = C: as C71 on sheet 1
C74 = C: OriginalSymbolOrigin: (2540,7620); COMP: -C-GRM1885C1H102JA01D
CN7 = BM02B_PASS_TFT_LF__SN_: Connector, 250V, 3A; MANUFACTURER: JST; COMP: -CN-BM02B-PASS-TFT_LF_SN; NOTE: 2pin; TIME: 16:53:54; UPDATEUSER: t5459927; SAVECOUNT: 1; SAVEAREA0: -5711,-10440,12927,3224; OriginalSymbolOrigin: (0,0); REFERENCE TEMPLATE: CN; INSTANCENAME: INS18317090
D22 = DEW: SAVEAREA0: -10024,-234,32508,20938; TIME: 14:49:55; UPDATEUSER: 19990028; UPDATETIME: 14:00:58; SAVECOUNT: 4; OriginalSymbolOrigin: (5080,17780); COMP: -D-1SS423_TE85L_F_AC
IC13 = OPA4325IPWR_4: COMP: -IC-OPA4325IPWR; TIME: 16:31:59; UPDATEUSER: t5459927; UPDATETIME: 16:35:50; SAVECOUNT: 11; SAVEAREA0: -17633,-13280,32685,23610; OriginalSymbolOrigin: (2540,10160); CaptureCellPackProp: OPA4325IPWR_4A; FUNCN: OPA4325IPWR_1
R78 R80 = R: OriginalSymbolOrigin: (5080,5080); VAL2: 100mW; COMP: -R-ERA3AEB103V
R79 R81 = R: OriginalSymbolOrigin: (5080,5080); VAL2: 100mW; COMP: -R-ERA3AEB203V
R82 = R: OriginalSymbolOrigin: (5080,5080); COMP: -R-ERJ3EKF2201V; VAL2: 100mW
R83 = R: as R15 on sheet 1
R84 = R: OriginalSymbolOrigin: (5080,5080); COMP: -R-RK73H1ETTP1003F; VAL2: 100mW
TP44-TP47 = TP: as TP2 on sheet 1
U?#4 = WAKU_DEF100: as U?#2 on sheet 2

## Sheet 5.SchDoc
size 420 x 297 mm
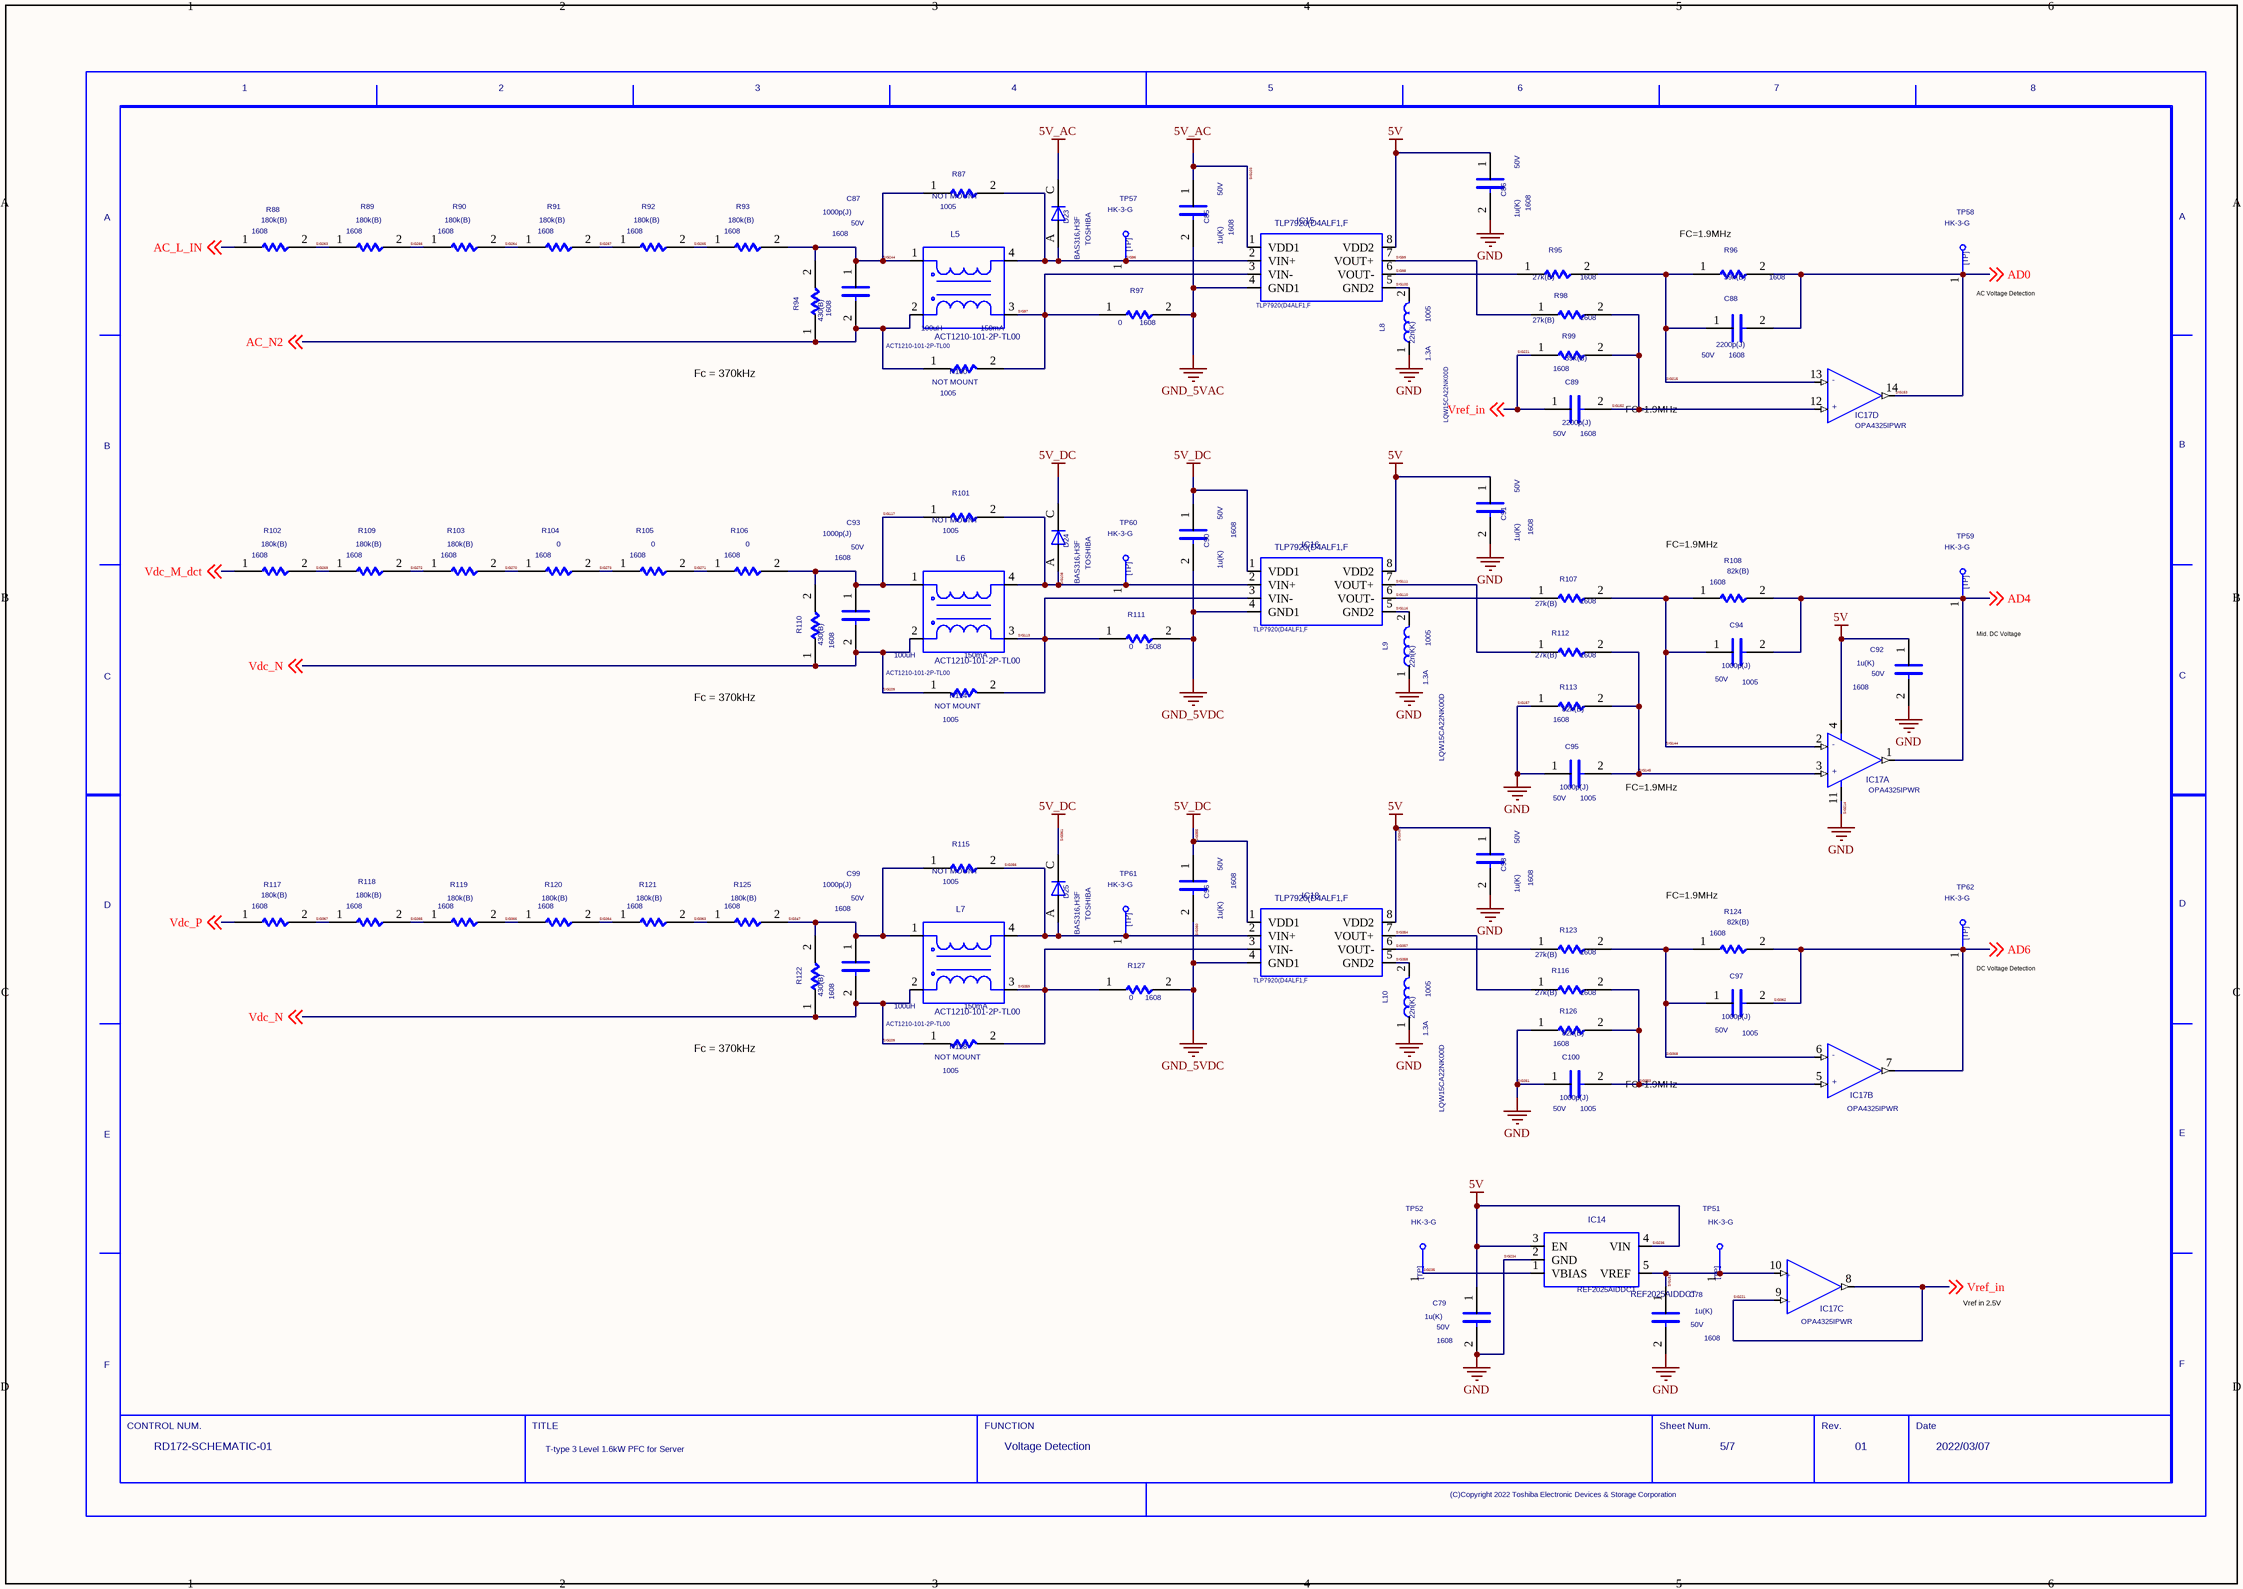
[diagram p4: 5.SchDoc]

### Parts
(Parts that share a designator on the sheet are numbered #1, #2 ... from top to bottom, then left to right.)
C78  SIZECODESMD: 1608  VAL2: 50V  VAL1: 1u(K)  (hidden comment: C)
C79  SIZECODESMD: 1608  VAL2: 50V  VAL1: 1u(K)  (hidden comment: C)
C85  SIZECODESMD: 1608  VAL2: 50V  VAL1: 1u(K)  (hidden comment: C)
C86  SIZECODESMD: 1608  VAL2: 50V  VAL1: 1u(K)  (hidden comment: C)
C87  SIZECODESMD: 1608  VAL2: 50V  VAL1: 1000p(J)  (hidden comment: C)
C88  SIZECODESMD: 1608  VAL2: 50V  VAL1: 2200p(J)  (hidden comment: C)
C89  SIZECODESMD: 1608  VAL2: 50V  VAL1: 2200p(J)  (hidden comment: C)
C90  SIZECODESMD: 1608  VAL2: 50V  VAL1: 1u(K)  (hidden comment: C)
C91  SIZECODESMD: 1608  VAL2: 50V  VAL1: 1u(K)  (hidden comment: C)
C92  SIZECODESMD: 1608  VAL2: 50V  VAL1: 1u(K)  (hidden comment: C)
C93  SIZECODESMD: 1608  VAL2: 50V  VAL1: 1000p(J)  (hidden comment: C)
C94  SIZECODESMD: 1005  VAL2: 50V  VAL1: 1000p(J)  (hidden comment: C)
C95  SIZECODESMD: 1005  VAL2: 50V  VAL1: 1000p(J)  (hidden comment: C)
C96  SIZECODESMD: 1608  VAL2: 50V  VAL1: 1u(K)  (hidden comment: C)
C97  SIZECODESMD: 1005  VAL2: 50V  VAL1: 1000p(J)  (hidden comment: C)
C98  SIZECODESMD: 1608  VAL2: 50V  VAL1: 1u(K)  (hidden comment: C)
C99  SIZECODESMD: 1608  VAL2: 50V  VAL1: 1000p(J)  (hidden comment: C)
C100  SIZECODESMD: 1005  VAL2: 50V  VAL1: 1000p(J)  (hidden comment: C)
D23  USERCOMPTEXT3: TOSHIBA  VAL3: BAS316,H3F  (hidden comment: D)
D24  USERCOMPTEXT3: TOSHIBA  VAL3: BAS316,H3F  (hidden comment: D)
D25  USERCOMPTEXT3: TOSHIBA  VAL3: BAS316,H3F  (hidden comment: D)
IC14  REF2025AIDDCT
IC15  TLP7920(D4ALF1,F
IC16  TLP7920(D4ALF1,F
IC17  VAL3: OPA4325IPWR  (hidden comment: OPA4325IPWR_4)  (parts A,B,C,D of 4)
IC18  TLP7920(D4ALF1,F
L5  ACT1210-101-2P-TL00  VAL1: 100uH
L6  ACT1210-101-2P-TL00  VAL1: 100uH
L7  ACT1210-101-2P-TL00  VAL1: 100uH
L8  VAL3: LQW15CA22NK00D  VAL2: 1.3A  VAL1: 22n(K)  SIZECODESMD: 1005  (hidden comment: L)
L9  VAL3: LQW15CA22NK00D  VAL2: 1.3A  VAL1: 22n(K)  SIZECODESMD: 1005  (hidden comment: L)
L10  VAL3: LQW15CA22NK00D  VAL2: 1.3A  VAL1: 22n(K)  SIZECODESMD: 1005  (hidden comment: L)
R87  SIZECODESMD: 1005  NOTMOUNT: NOT MOUNT  (hidden comment: R)
R88  SIZECODESMD: 1608  VAL1: 180k(B)  (hidden comment: R)
R89  SIZECODESMD: 1608  VAL1: 180k(B)  (hidden comment: R)
R90  SIZECODESMD: 1608  VAL1: 180k(B)  (hidden comment: R)
R91  SIZECODESMD: 1608  VAL1: 180k(B)  (hidden comment: R)
R92  SIZECODESMD: 1608  VAL1: 180k(B)  (hidden comment: R)
R93  SIZECODESMD: 1608  VAL1: 180k(B)  (hidden comment: R)
R94  SIZECODESMD: 1608  VAL1: 430(B)  (hidden comment: R)
R95  SIZECODESMD: 1608  VAL1: 27k(B)  (hidden comment: R)
R96  SIZECODESMD: 1608  VAL1: 39k(B)  (hidden comment: R)
R97  SIZECODESMD: 1608  VAL1: 0  (hidden comment: R)
R98  SIZECODESMD: 1608  VAL1: 27k(B)  (hidden comment: R)
R99  SIZECODESMD: 1608  VAL1: 39k(B)  (hidden comment: R)
R100  SIZECODESMD: 1005  NOTMOUNT: NOT MOUNT  (hidden comment: R)
R101  SIZECODESMD: 1005  NOTMOUNT: NOT MOUNT  (hidden comment: R)
R102  SIZECODESMD: 1608  VAL1: 180k(B)  (hidden comment: R)
R103  SIZECODESMD: 1608  VAL1: 180k(B)  (hidden comment: R)
R104  SIZECODESMD: 1608  VAL1: 0  (hidden comment: R)
R105  SIZECODESMD: 1608  VAL1: 0  (hidden comment: R)
R106  SIZECODESMD: 1608  VAL1: 0  (hidden comment: R)
R107  SIZECODESMD: 1608  VAL1: 27k(B)  (hidden comment: R)
R108  SIZECODESMD: 1608  VAL1: 82k(B)  (hidden comment: R)
R109  SIZECODESMD: 1608  VAL1: 180k(B)  (hidden comment: R)
R110  SIZECODESMD: 1608  VAL1: 430(B)  (hidden comment: R)
R111  SIZECODESMD: 1608  VAL1: 0  (hidden comment: R)
R112  SIZECODESMD: 1608  VAL1: 27k(B)  (hidden comment: R)
R113  SIZECODESMD: 1608  VAL1: 82k(B)  (hidden comment: R)
R114  SIZECODESMD: 1005  NOTMOUNT: NOT MOUNT  (hidden comment: R)
R115  SIZECODESMD: 1005  NOTMOUNT: NOT MOUNT  (hidden comment: R)
R116  SIZECODESMD: 1608  VAL1: 27k(B)  (hidden comment: R)
R117  SIZECODESMD: 1608  VAL1: 180k(B)  (hidden comment: R)
R118  SIZECODESMD: 1608  VAL1: 180k(B)  (hidden comment: R)
R119  SIZECODESMD: 1608  VAL1: 180k(B)  (hidden comment: R)
R120  SIZECODESMD: 1608  VAL1: 180k(B)  (hidden comment: R)
R121  SIZECODESMD: 1608  VAL1: 180k(B)  (hidden comment: R)
R122  SIZECODESMD: 1608  VAL1: 430(B)  (hidden comment: R)
R123  SIZECODESMD: 1608  VAL1: 27k(B)  (hidden comment: R)
R124  SIZECODESMD: 1608  VAL1: 82k(B)  (hidden comment: R)
R125  SIZECODESMD: 1608  VAL1: 180k(B)  (hidden comment: R)
R126  SIZECODESMD: 1608  VAL1: 82k(B)  (hidden comment: R)
R127  SIZECODESMD: 1608  VAL1: 0  (hidden comment: R)
R128  SIZECODESMD: 1005  NOTMOUNT: NOT MOUNT  (hidden comment: R)
TP51  VAL3: HK-3-G  (hidden comment: TP)
TP52  VAL3: HK-3-G  (hidden comment: TP)
TP57  VAL3: HK-3-G  (hidden comment: TP)
TP58  VAL3: HK-3-G  (hidden comment: TP)
TP59  VAL3: HK-3-G  (hidden comment: TP)
TP60  VAL3: HK-3-G  (hidden comment: TP)
TP61  VAL3: HK-3-G  (hidden comment: TP)
TP62  VAL3: HK-3-G  (hidden comment: TP)
U?#5  DATE: 2022/03/07  REVISION: 01  SHEETNUMBER: 5/7  FUNCTION: Voltage Detection  TITLE: T-type 3 Level 1.6kW PFC for Server  DRAWINGNUMBER: RD172-SCHEMATIC-01  (hidden comment: WAKU_DEF100)

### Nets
5V: C79.1 C86.1 C91.1 C92.1 C98.1 IC14.3(EN) IC14.4(VIN) IC15.8(VDD2) IC16.8(VDD2) IC17.4(V+) IC18.8(VDD2)  [also labelled SIG236, SIG349]  [project net SIG177]
GND_5VAC: C85.2 IC15.4(GND1) R97.2  [project net SIG299]
SIG103: C85.1 D23.C IC15.1(VDD1)  [also labelled 5V_AC]
SIG157: C78.2 C79.2 C86.2 C91.2 C92.2 C95.1 C98.2 C100.1 IC14.2(GND) IC17.11(V-) L8.1 L9.1 L10.1 R113.1 R126.1  [also labelled GND, SIG214, SIG234, SIG351]
SIG355: C90.1 C96.1 D24.C D25.C IC16.1(VDD1) IC18.1(VDD1)  [also labelled 5V_DC, SIG361]
SIG360: C90.2 C96.2 IC16.4(GND1) IC18.4(GND1) R111.2 R127.2  [also labelled GND_5VDC]
AC_L_IN: R88.1 ; off-sheet AC_L_IN
AC_N2: C87.2 L5.2 R94.1 R100.1 ; off-sheet AC_N2
AD4: C94.2 IC17.1(OUT) R108.2 TP59.1 ; off-sheet AD4
SIG96: D23.A IC15.2(VIN+) L5.4 R87.2 TP57.1
SIG97: IC15.3(VIN-) L5.3 R97.1 R100.2
SIG98: IC15.6(VOUT-) R95.1
SIG99: IC15.7(VOUT+) R98.1
SIG100: IC15.5(GND2) L8.2
SIG108: D24.A IC16.2(VIN+) L6.4 R101.2 TP60.1
SIG110: IC16.6(VOUT-) R107.1
SIG111: IC16.7(VOUT+) R112.1
SIG113: IC16.3(VIN-) L6.3 R111.1 R114.2
SIG116: IC16.5(GND2) L9.2
SIG117: C93.1 L6.1 R101.1 R106.2 R110.2
SIG144: C94.1 IC17.2(IN-) R107.2 R108.1
SIG145: C95.2 IC17.3(IN+) R112.2 R113.2
SIG151: C78.1 IC14.5(VREF) IC17.10 TP51.1
SIG152: C89.2 IC17.12 R98.2 R99.2
SIG153: C88.2 IC17.14 R96.2 TP58.1 ; off-sheet AD0  [also labelled AD0]
SIG209: C93.2 C99.2 L6.2 L7.2 R110.1 R114.1 R122.1 R128.1 ; off-sheet Vdc_N  [also labelled Vdc_N]
SIG215: C88.1 IC17.13 R95.2 R96.1
SIG221: C89.1 IC17.8 IC17.9 R99.1 ; off-sheet Vref_in  [also labelled Vref_in]
SIG235: IC14.1(VBIAS) TP52.1
SIG244: C87.1 L5.1 R87.1 R93.2 R94.2
SIG263: R88.2 R89.1
SIG264: R90.2 R91.1
SIG265: R92.2 R93.1
SIG266: R89.2 R90.1
SIG267: R91.2 R92.1
SIG269: R102.2 R109.1
SIG270: R103.2 R104.1
SIG271: R105.2 R106.1
SIG272: R103.1 R109.2
SIG273: R104.2 R105.1
SIG347: C99.1 L7.1 R115.1 R122.2 R125.2
SIG353: C100.2 IC17.5 R116.2 R126.2
SIG354: IC18.7(VOUT+) R116.1
SIG356: D25.A IC18.2(VIN+) L7.4 R115.2 TP61.1
SIG357: IC18.6(VOUT-) R123.1
SIG358: IC18.5(GND2) L10.2
SIG359: IC18.3(VIN-) L7.3 R127.1 R128.2
SIG362: C97.2 IC17.7 R124.2 TP62.1 ; off-sheet AD6  [also labelled AD6]
SIG363: R121.2 R125.1
SIG364: R120.2 R121.1
SIG365: R118.2 R119.1
SIG366: R119.2 R120.1
SIG367: R117.2 R118.1
SIG368: C97.1 IC17.6 R123.2 R124.1
Vdc_M_dct: R102.1 ; off-sheet Vdc_M_dct
Vdc_P: R117.1 ; off-sheet Vdc_P

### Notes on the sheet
- (near R96) FC=1.9MHz
- (near TP58) AC Voltage Detection
- Fc = 370kHz
- FC=1.9MHz
- (near R108) FC=1.9MHz
- (near TP59) Mid. DC Voltage
  Detection
- (near C95) FC=1.9MHz
- (near R124) FC=1.9MHz
- (near TP62) DC Voltage Detection
- Vref in 2.5V

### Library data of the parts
C78 C79 C85 C86 C90-C92 C96 C98 = C: as C4 on sheet 1
C87 C93 C99 = C: as C74 on sheet 4
C88 C89 = C: OriginalSymbolOrigin: (2540,7620); COMP: -C-GRM1882C1H222JA01D
C94 C95 C97 C100 = C: OriginalSymbolOrigin: (2540,7620); COMP: -C-GRM1555C1H102JA01D
D23-D25 = D: as D2 on sheet 1
IC14 = REF2025AIDDCT: Voltage References; MANUFACTURER: Texas Instruments; COMP: -IC-REF2025AIDDCT; TIME: 16:53:54; UPDATEUSER: t5459927; UPDATETIME: 16:09:37; SAVECOUNT: 2; SAVEAREA0: -3467,-13658,20665,4033; OriginalSymbolOrigin: (0,0)
IC15 IC16 IC18 = TLP7920_D4ALF1_F_0: Photocoupler; MANUFACTURER: TOSHIBA; COMP: -IC-TLP7920_LF5_TP5; TIME: 16:53:58; UPDATEUSER: t5459927; UPDATETIME: 16:21:24; SAVECOUNT: 2; SAVEAREA0: -6097,-17212,23397,4411; OriginalSymbolOrigin: (0,0)
IC17 = OPA4325IPWR_4: as IC13 on sheet 4
L5-L7 = ACT1210_101_2P_TL00: 150mA; MAKER: TDK; COMP: -L-ACT1210-101-2P-TL00; TIME: 16:53:54; UPDATEUSER: t5459927; SAVECOUNT: 1; SAVEAREA0: -3836,-15544,18528,852; OriginalSymbolOrigin: (0,0); INSTANCENAME: INS18165735
L8-L10 = L: OriginalSymbolOrigin: (2540,5080); COMP: -L-LQW15CA22NK00
R87 R100 R101 R114 R115 R128 = R: OriginalSymbolOrigin: (5080,5080); COMP: -R-NC_R1005
R88-R93 R102 R103 R109 R117-R121 R125 = R: OriginalSymbolOrigin: (5080,5080); COMP: -R-ERA3AEB184V; VAL2: 100mW
R94 R110 R122 = R: OriginalSymbolOrigin: (5080,5080); COMP: -R-ERA3AEB431V; VAL2: 100mW
R95 R98 R107 R112 R116 R123 = R: OriginalSymbolOrigin: (5080,5080); COMP: -R-ERA3ARB273V; VAL2: 100mW
R96 R99 = R: OriginalSymbolOrigin: (5080,5080); COMP: -R-ERA3AEB393V; VAL2: 100mW
R97 R104-R106 R111 R127 = R: OriginalSymbolOrigin: (5080,5080); COMP: -R-RK73Z1JTTD; VAL2: 1A
R108 R113 R124 R126 = R: OriginalSymbolOrigin: (5080,5080); COMP: -R-ERA3ARB823V; VAL2: 100mW
TP51 TP52 TP57-TP62 = TP: as TP2 on sheet 1
U?#5 = WAKU_DEF100: PLOTTIME: HH:MM; SAVEAREA0: 148187,-66180,486823,89919; TIME: 14:30:25; UPDATEUSER: t5459927; UPDATETIME: 09:34:23; SAVECOUNT: 6; OriginalSymbolOrigin: (10160,284480)

## Sheet 6.SchDoc
size 420 x 297 mm
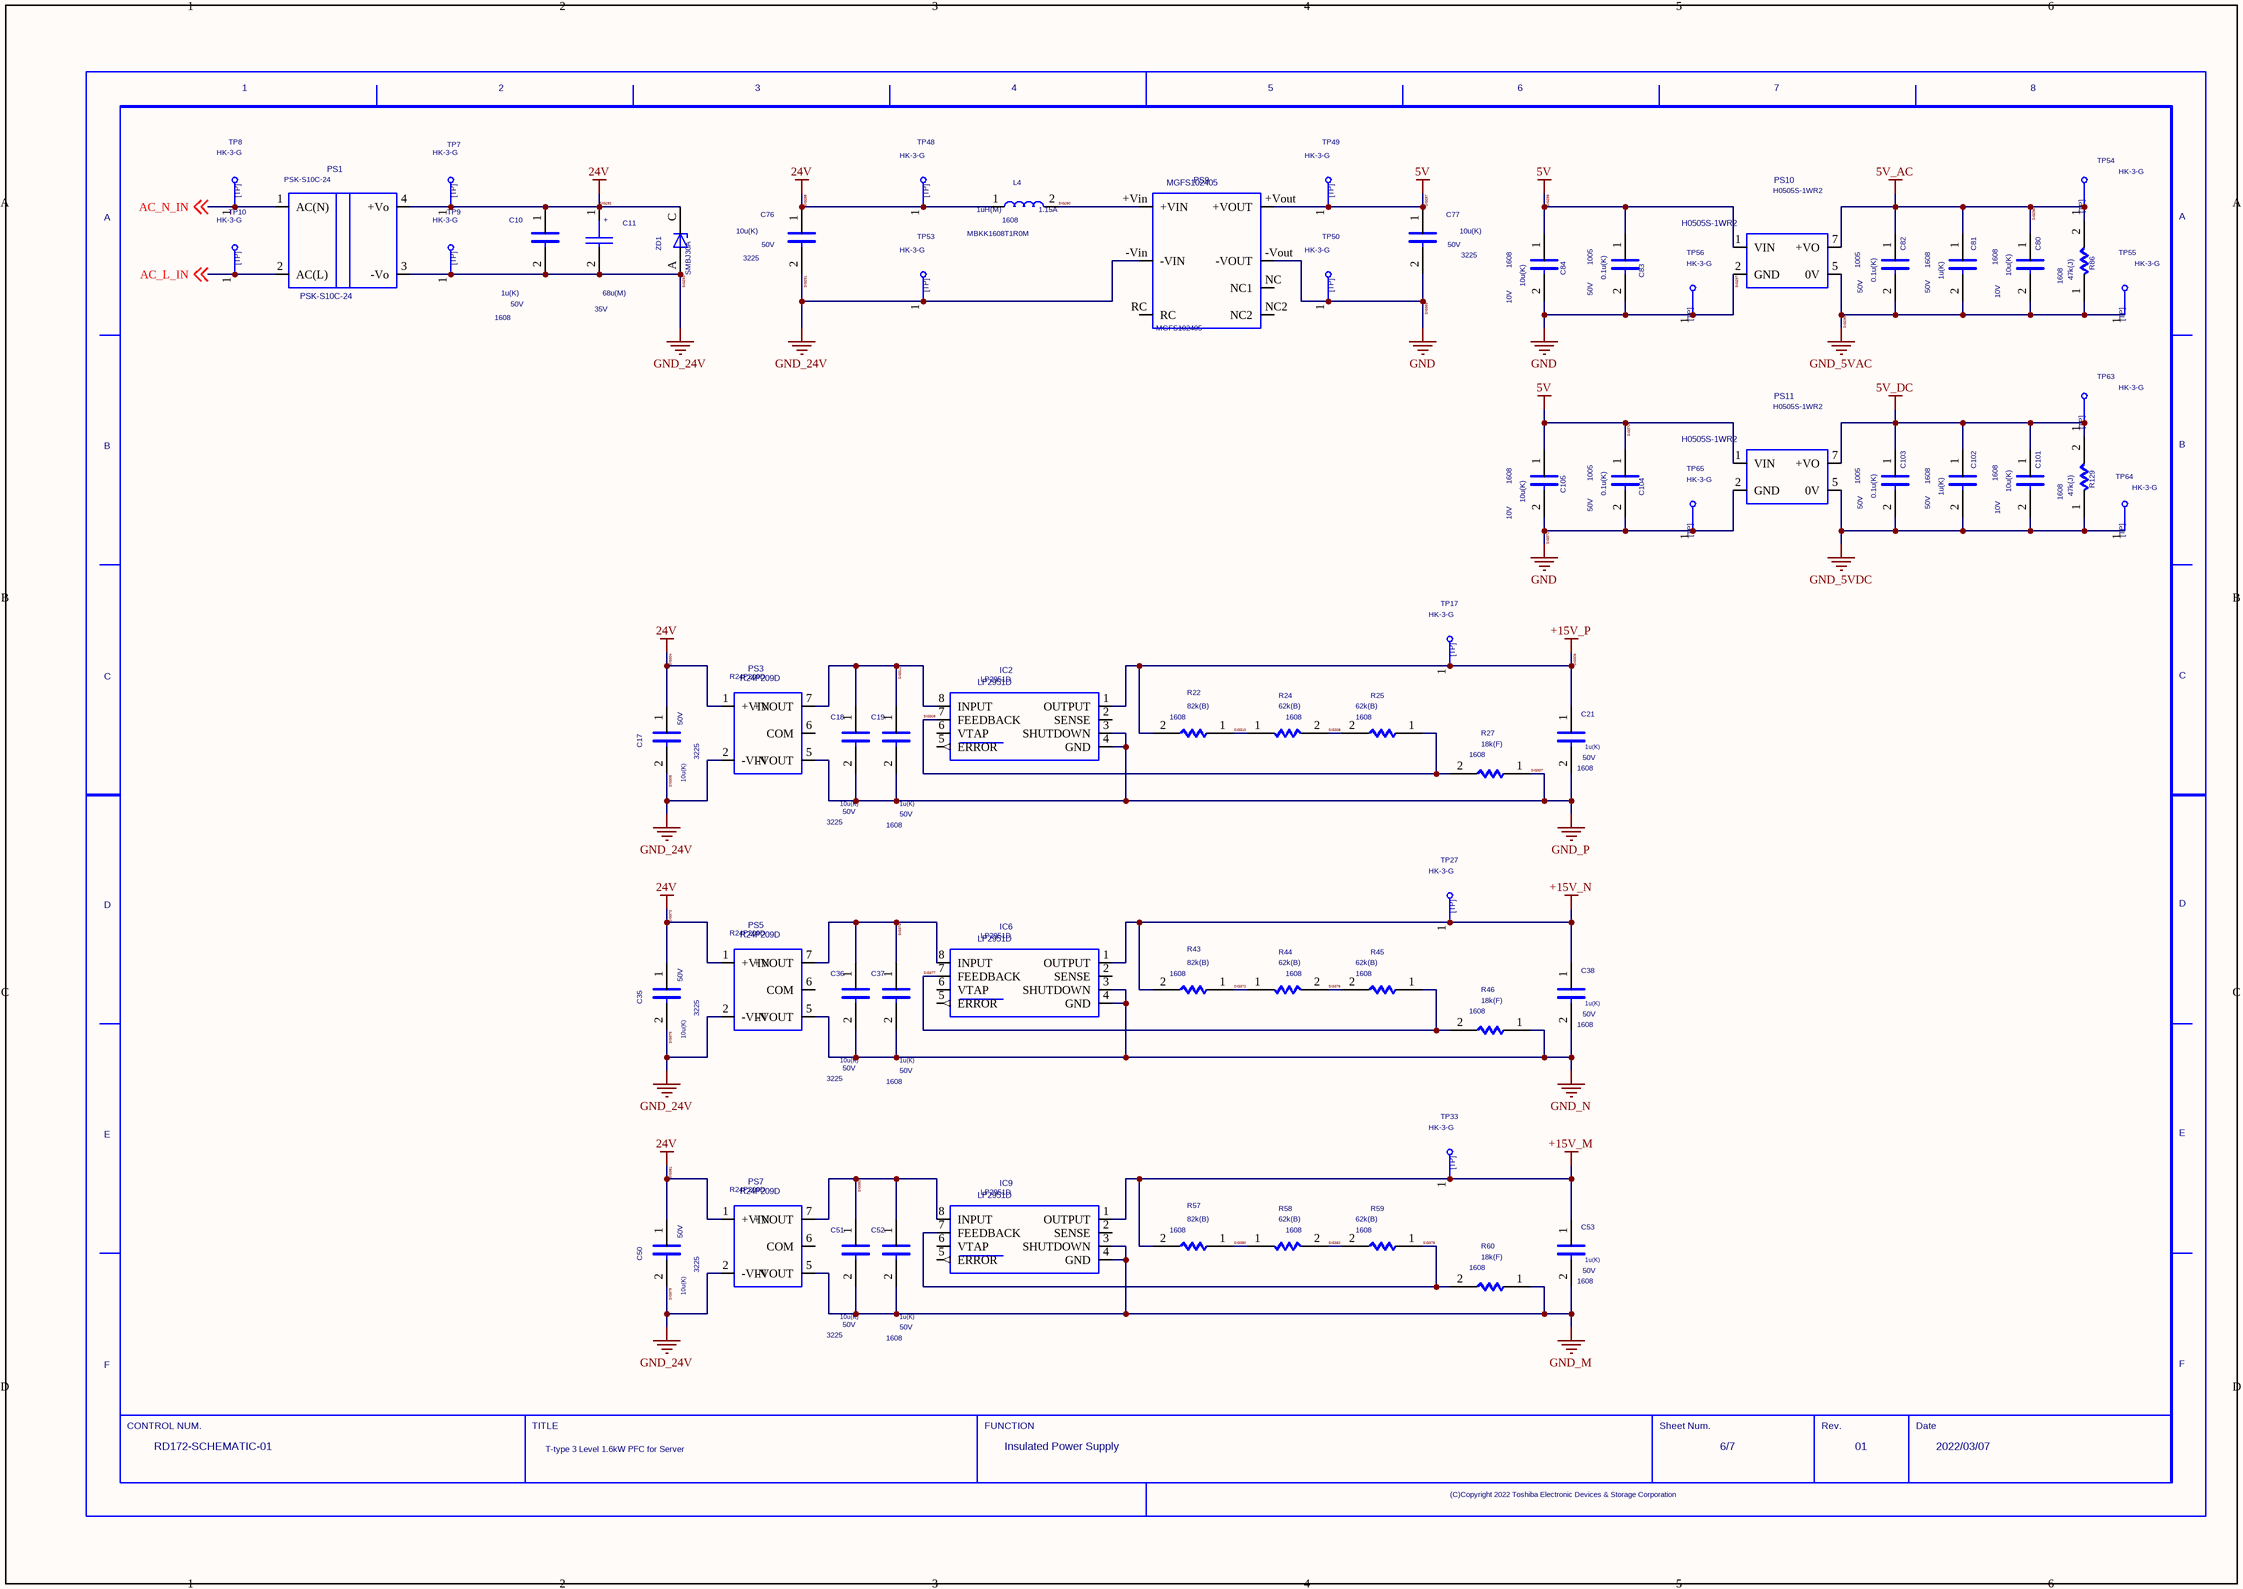
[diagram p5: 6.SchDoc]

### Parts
(Parts that share a designator on the sheet are numbered #1, #2 ... from top to bottom, then left to right.)
C10  SIZECODESMD: 1608  VAL2: 50V  VAL1: 1u(K)  (hidden comment: C)
C11  VAL2: 35V  VAL1: 68u(M)  (hidden comment: CP)
C17  SIZECODESMD: 3225  VAL2: 50V  VAL1: 10u(K)  (hidden comment: C)
C18  SIZECODESMD: 3225  VAL2: 50V  VAL1: 10u(K)  (hidden comment: C)
C19  SIZECODESMD: 1608  VAL2: 50V  VAL1: 1u(K)  (hidden comment: C)
C21  SIZECODESMD: 1608  VAL2: 50V  VAL1: 1u(K)  (hidden comment: C)
C35  SIZECODESMD: 3225  VAL2: 50V  VAL1: 10u(K)  (hidden comment: C)
C36  SIZECODESMD: 3225  VAL2: 50V  VAL1: 10u(K)  (hidden comment: C)
C37  SIZECODESMD: 1608  VAL2: 50V  VAL1: 1u(K)  (hidden comment: C)
C38  SIZECODESMD: 1608  VAL2: 50V  VAL1: 1u(K)  (hidden comment: C)
C50  SIZECODESMD: 3225  VAL2: 50V  VAL1: 10u(K)  (hidden comment: C)
C51  SIZECODESMD: 3225  VAL2: 50V  VAL1: 10u(K)  (hidden comment: C)
C52  SIZECODESMD: 1608  VAL2: 50V  VAL1: 1u(K)  (hidden comment: C)
C53  SIZECODESMD: 1608  VAL2: 50V  VAL1: 1u(K)  (hidden comment: C)
C76  SIZECODESMD: 3225  VAL2: 50V  VAL1: 10u(K)  (hidden comment: C)
C77  SIZECODESMD: 3225  VAL2: 50V  VAL1: 10u(K)  (hidden comment: C)
C80  SIZECODESMD: 1608  VAL2: 10V  VAL1: 10u(K)  (hidden comment: C)
C81  SIZECODESMD: 1608  VAL2: 50V  VAL1: 1u(K)  (hidden comment: C)
C82  SIZECODESMD: 1005  VAL2: 50V  VAL1: 0.1u(K)  (hidden comment: C)
C83  SIZECODESMD: 1005  VAL2: 50V  VAL1: 0.1u(K)  (hidden comment: C)
C84  SIZECODESMD: 1608  VAL2: 10V  VAL1: 10u(K)  (hidden comment: C)
C101  SIZECODESMD: 1608  VAL2: 10V  VAL1: 10u(K)  (hidden comment: C)
C102  SIZECODESMD: 1608  VAL2: 50V  VAL1: 1u(K)  (hidden comment: C)
C103  SIZECODESMD: 1005  VAL2: 50V  VAL1: 0.1u(K)  (hidden comment: C)
C104  SIZECODESMD: 1005  VAL2: 50V  VAL1: 0.1u(K)  (hidden comment: C)
C105  SIZECODESMD: 1608  VAL2: 10V  VAL1: 10u(K)  (hidden comment: C)
IC2  LP2951D
IC6  LP2951D
IC9  LP2951D
L4  VAL2: 1.15A  SIZECODESMD: 1608  VAL1: 1uH(M)  VAL3: MBKK1608T1R0M  (hidden comment: L)
PS1  PSK-S10C-24
PS3  R24P209D
PS5  R24P209D
PS7  R24P209D
PS9  MGFS102405
PS10  H0505S-1WR2
PS11  H0505S-1WR2
R22  SIZECODESMD: 1608  VAL1: 82k(B)  (hidden comment: R)
R24  SIZECODESMD: 1608  VAL1: 62k(B)  (hidden comment: R)
R25  SIZECODESMD: 1608  VAL1: 62k(B)  (hidden comment: R)
R27  SIZECODESMD: 1608  VAL1: 18k(F)  (hidden comment: R)
R43  SIZECODESMD: 1608  VAL1: 82k(B)  (hidden comment: R)
R44  SIZECODESMD: 1608  VAL1: 62k(B)  (hidden comment: R)
R45  SIZECODESMD: 1608  VAL1: 62k(B)  (hidden comment: R)
R46  SIZECODESMD: 1608  VAL1: 18k(F)  (hidden comment: R)
R57  SIZECODESMD: 1608  VAL1: 82k(B)  (hidden comment: R)
R58  SIZECODESMD: 1608  VAL1: 62k(B)  (hidden comment: R)
R59  SIZECODESMD: 1608  VAL1: 62k(B)  (hidden comment: R)
R60  SIZECODESMD: 1608  VAL1: 18k(F)  (hidden comment: R)
R86  SIZECODESMD: 1608  VAL1: 47k(J)  (hidden comment: R)
R129  SIZECODESMD: 1608  VAL1: 47k(J)  (hidden comment: R)
TP7  VAL3: HK-3-G  (hidden comment: TP)
TP8  VAL3: HK-3-G  (hidden comment: TP)
TP9  VAL3: HK-3-G  (hidden comment: TP)
TP10  VAL3: HK-3-G  (hidden comment: TP)
TP17  VAL3: HK-3-G  (hidden comment: TP)
TP27  VAL3: HK-3-G  (hidden comment: TP)
TP33  VAL3: HK-3-G  (hidden comment: TP)
TP48  VAL3: HK-3-G  (hidden comment: TP)
TP49  VAL3: HK-3-G  (hidden comment: TP)
TP50  VAL3: HK-3-G  (hidden comment: TP)
TP53  VAL3: HK-3-G  (hidden comment: TP)
TP54  VAL3: HK-3-G  (hidden comment: TP)
TP55  VAL3: HK-3-G  (hidden comment: TP)
TP56  VAL3: HK-3-G  (hidden comment: TP)
TP63  VAL3: HK-3-G  (hidden comment: TP)
TP64  VAL3: HK-3-G  (hidden comment: TP)
TP65  VAL3: HK-3-G  (hidden comment: TP)
U?#6  DATE: 2022/03/07  REVISION: 01  SHEETNUMBER: 6/7  TITLE: T-type 3 Level 1.6kW PFC for Server  DRAWINGNUMBER: RD172-SCHEMATIC-01  FUNCTION: Insulated Power Supply  (hidden comment: WAKU_DEF100)
ZD1  VAL3: SMBJ30A  (hidden comment: ZD)

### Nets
5V: C77.1 C83.1 C84.1 C104.1 C105.1 PS9.+Vout(+VOUT) PS10.1(VIN) PS11.1(VIN) TP49.1  [also labelled SIG287, SIG298, SIG370]  [project net SIG177]
5V_AC: C80.1 C81.1 C82.1 PS10.7(+VO) R86.2 TP54.1  [also labelled SIG296]  [project net SIG103]
5V_DC: C101.1 C102.1 C103.1 PS11.7(+VO) R129.2 TP63.1  [project net SIG355]
24V: C10.1 C11.1 C17.1 C35.1 C50.1 C76.1 L4.1 PS1.4(+Vo) PS3.1(+VIN) PS5.1(+VIN) PS7.1(+VIN) TP7.1 TP48.1 ZD1.C  [also labelled SIG288, SIG292, SIG304, SIG373, SIG381]  [project net SIG18]
+15V_M: C53.1 IC9.1(OUTPUT) R57.2 TP33.1  [project net SIG285]
+15V_N: C38.1 IC6.1(OUTPUT) R43.2 TP27.1
GND: C77.2 C83.2 C84.2 C104.2 C105.2 PS9.-Vout(-VOUT) PS10.2(GND) PS11.2(GND) TP50.1 TP56.1 TP65.1  [also labelled SIG297, SIG369, SIG371]  [project net SIG157]
GND_5VDC: C101.2 C102.2 C103.2 PS11.5(0V) R129.1 TP64.1  [project net SIG360]
GND_24V: C10.2 C11.2 C17.2 C35.2 C50.2 C76.2 PS1.3(-Vo) PS3.2(-VIN) PS5.2(-VIN) PS7.2(-VIN) PS9.-Vin(-VIN) TP9.1 TP53.1 ZD1.A  [also labelled SIG291, SIG293, SIG305, SIG375, SIG379]  [project net SIG17]
GND_M: C51.2 C52.2 C53.2 IC9.3(SHUTDOWN) IC9.4(GND) PS7.5(-VOUT) R60.1  [project net SIG213]
GND_N: C36.2 C37.2 C38.2 IC6.3(SHUTDOWN) IC6.4(GND) PS5.5(-VOUT) R46.1
SIG299: C80.2 C81.2 C82.2 PS10.5(0V) R86.1 TP55.1  [also labelled GND_5VAC]
SIG306: C21.1 IC2.1(OUTPUT) R22.2 TP17.1  [also labelled +15V_P]
SIG307: C18.2 C19.2 C21.2 IC2.3(SHUTDOWN) IC2.4(GND) PS3.5(-VOUT) R27.1  [also labelled GND_P]
AC_L_IN: PS1.2(AC(L)) TP10.1 ; off-sheet AC_L_IN
AC_N_IN: PS1.1(AC(N)) TP8.1 ; off-sheet AC_N_IN
SIG290: L4.2 PS9.+Vin(+VIN)
SIG308: R24.2 R25.2
SIG309: IC2.7(FEEDBACK) R25.1 R27.2
SIG310: R22.1 R24.1
SIG311: C18.1 C19.1 IC2.8(INPUT) PS3.7(+VOUT)
SIG372: R43.1 R44.1
SIG374: C36.1 C37.1 IC6.8(INPUT) PS5.7(+VOUT)
SIG376: R44.2 R45.2
SIG377: IC6.7(FEEDBACK) R45.1 R46.2
SIG378: IC9.7(FEEDBACK) R59.1 R60.2
SIG380: R57.1 R58.1
SIG382: R58.2 R59.2
SIG383: C51.1 C52.1 IC9.8(INPUT) PS7.7(+VOUT)

Not connected (* = marked no-connect by the designer): IC2 2(SENSE) 5(ERROR) 6(VTAP); IC6 2(SENSE) 5(ERROR) 6(VTAP); IC9 2(SENSE) 5(ERROR) 6(VTAP); PS3 6(COM); PS5 6(COM); PS7 6(COM); PS9 NC(NC1) NC2 RC

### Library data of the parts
C10 C19 C21 C37 C38 C52 C53 C81 C102 = C: as C4 on sheet 1
C11 = CP: SAVEAREA0: -1450,-153,20294,13055; SAVECOUNT: 52; TIME: 15:02:55; UPDATEUSER: fukuda-y; UPDATETIME: 16:13:42; OriginalSymbolOrigin: (2540,10160); COMP: -C-EEHZC1V680XP
C17 C18 C35 C36 C50 C51 C76 C77 = C: as C15 on sheet 2
C80 C84 C101 C105 = C: OriginalSymbolOrigin: (2540,7620); COMP: -C-GRM188D71A106KA73D
C82 C83 C103 C104 = C: as C71 on sheet 1
IC2 IC6 IC9 = LP2951D: Voltage Regulators; MANUFACTURER: Txsas Instruments; COMP: -IC-LP2951D; TIME: 16:53:55; UPDATEUSER: t5459927; UPDATETIME: 16:15:29; SAVECOUNT: 3; SAVEAREA0: -15946,-25147,36340,13186; OriginalSymbolOrigin: (0,0)
L4 = L: OriginalSymbolOrigin: (2540,5080); COMP: -L-MBKK1608T1R0M
PS1 = PSK_S10C_24: AC/DC Converter; MANUFACTURER: CUI INC; COMP: -PS-PSK-S10C-24; TIME: 16:53:55; UPDATEUSER: t5459927; UPDATETIME: 14:43:43; SAVECOUNT: 2; SAVEAREA0: -3577,-18400,23236,1258; OriginalSymbolOrigin: (0,0)
PS3 PS5 PS7 = R24P209D: DC/DC Converter; MANUFACTURER: RECOM; COMP: -PS-R24P209D; TIME: 16:53:55; UPDATEUSER: t5459927; UPDATETIME: 16:11:38; SAVECOUNT: 2; SAVEAREA0: -5083,-15544,17282,852; OriginalSymbolOrigin: (0,0)
PS9 = MGFS102405: DC/DC Converter; MANUFACTURER: COSEL; COMP: -PS-MGFS102405_PIN; TIME: 16:53:55; UPDATEUSER: t5459927; UPDATETIME: 16:09:02; SAVECOUNT: 2; SAVEAREA0: -8909,-25908,28368,1421; OriginalSymbolOrigin: (0,0)
PS10 PS11 = H0505S_1WR2: DC/DC Converter; MANUFACTURER: MORNSUN; COMP: -PS-H0505S-1WR2; TIME: 16:53:55; UPDATEUSER: t5459927; UPDATETIME: 14:51:35; SAVECOUNT: 2; SAVEAREA0: -3365,-12675,18085,3050; OriginalSymbolOrigin: (0,0)
R22 R43 R57 = R: OriginalSymbolOrigin: (5080,5080); VAL2: 100mW; COMP: -R-ERA3ARB823V
R24 R25 R44 R45 R58 R59 = R: OriginalSymbolOrigin: (5080,5080); VAL2: 100mW; COMP: -R-ERA3APB623V
R27 R46 R60 = R: OriginalSymbolOrigin: (5080,5080); VAL2: 100mW; COMP: -R-RK73H1JTTD1802F
R86 R129 = R: OriginalSymbolOrigin: (5080,5080); COMP: -R-RK73B1JTTD473J; VAL2: 100mW
TP7-TP10 TP17 TP27 TP33 TP48-TP50 TP53-TP56 TP63-TP65 = TP: as TP2 on sheet 1
U?#6 = WAKU_DEF100: PLOTTIME: HH:MM; SAVEAREA0: -45080,-4508,463680,304612; TIME: 16:20:58; UPDATEUSER: t5459927; UPDATETIME: 09:34:25; SAVECOUNT: 7; OriginalSymbolOrigin: (10160,284480)
ZD1 = ZD: SAVEAREA0: -4630,-153,17114,13055; TIME: 14:49:55; UPDATEUSER: fukuda-y; UPDATETIME: 08:18:42; SAVECOUNT: 6; OriginalSymbolOrigin: (5080,5080); COMP: -D-SMBJ30A_AC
